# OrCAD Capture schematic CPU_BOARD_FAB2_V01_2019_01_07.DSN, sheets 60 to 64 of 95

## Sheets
60 045 DDR4 SODIMM CHA_1: size B
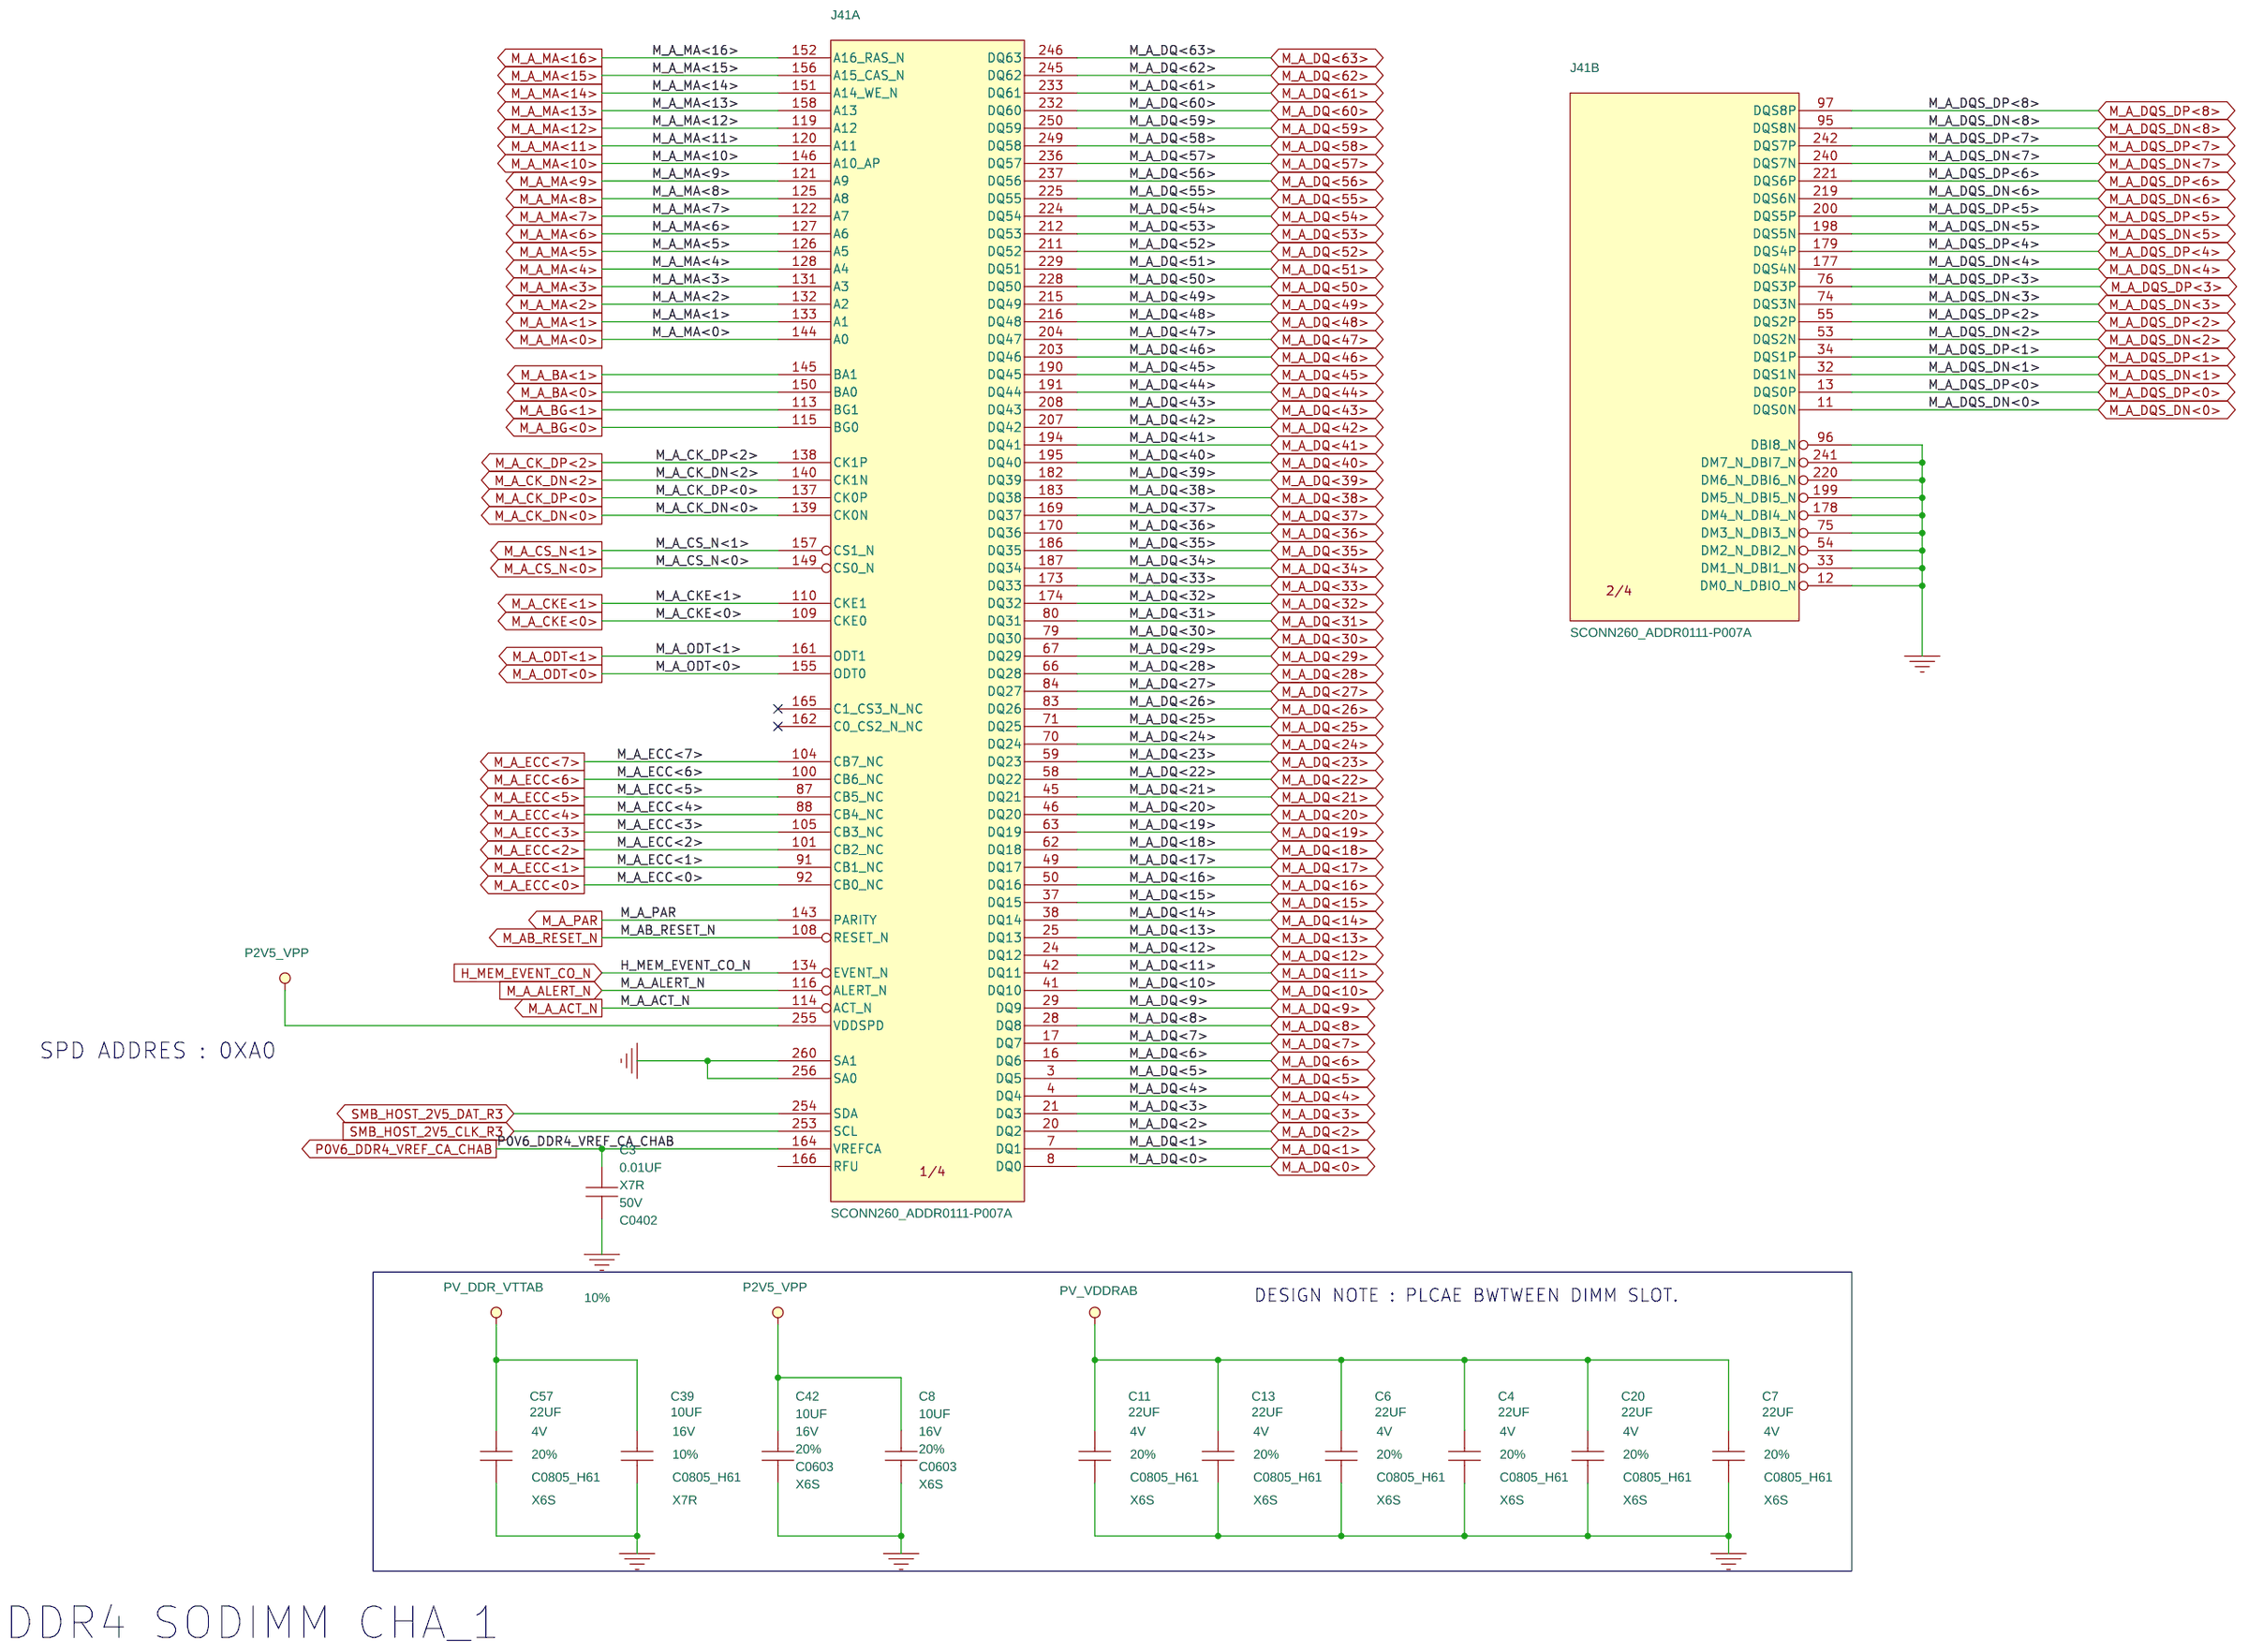
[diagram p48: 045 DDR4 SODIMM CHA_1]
61 047 DDR4 SODIMM CHB_1: size B
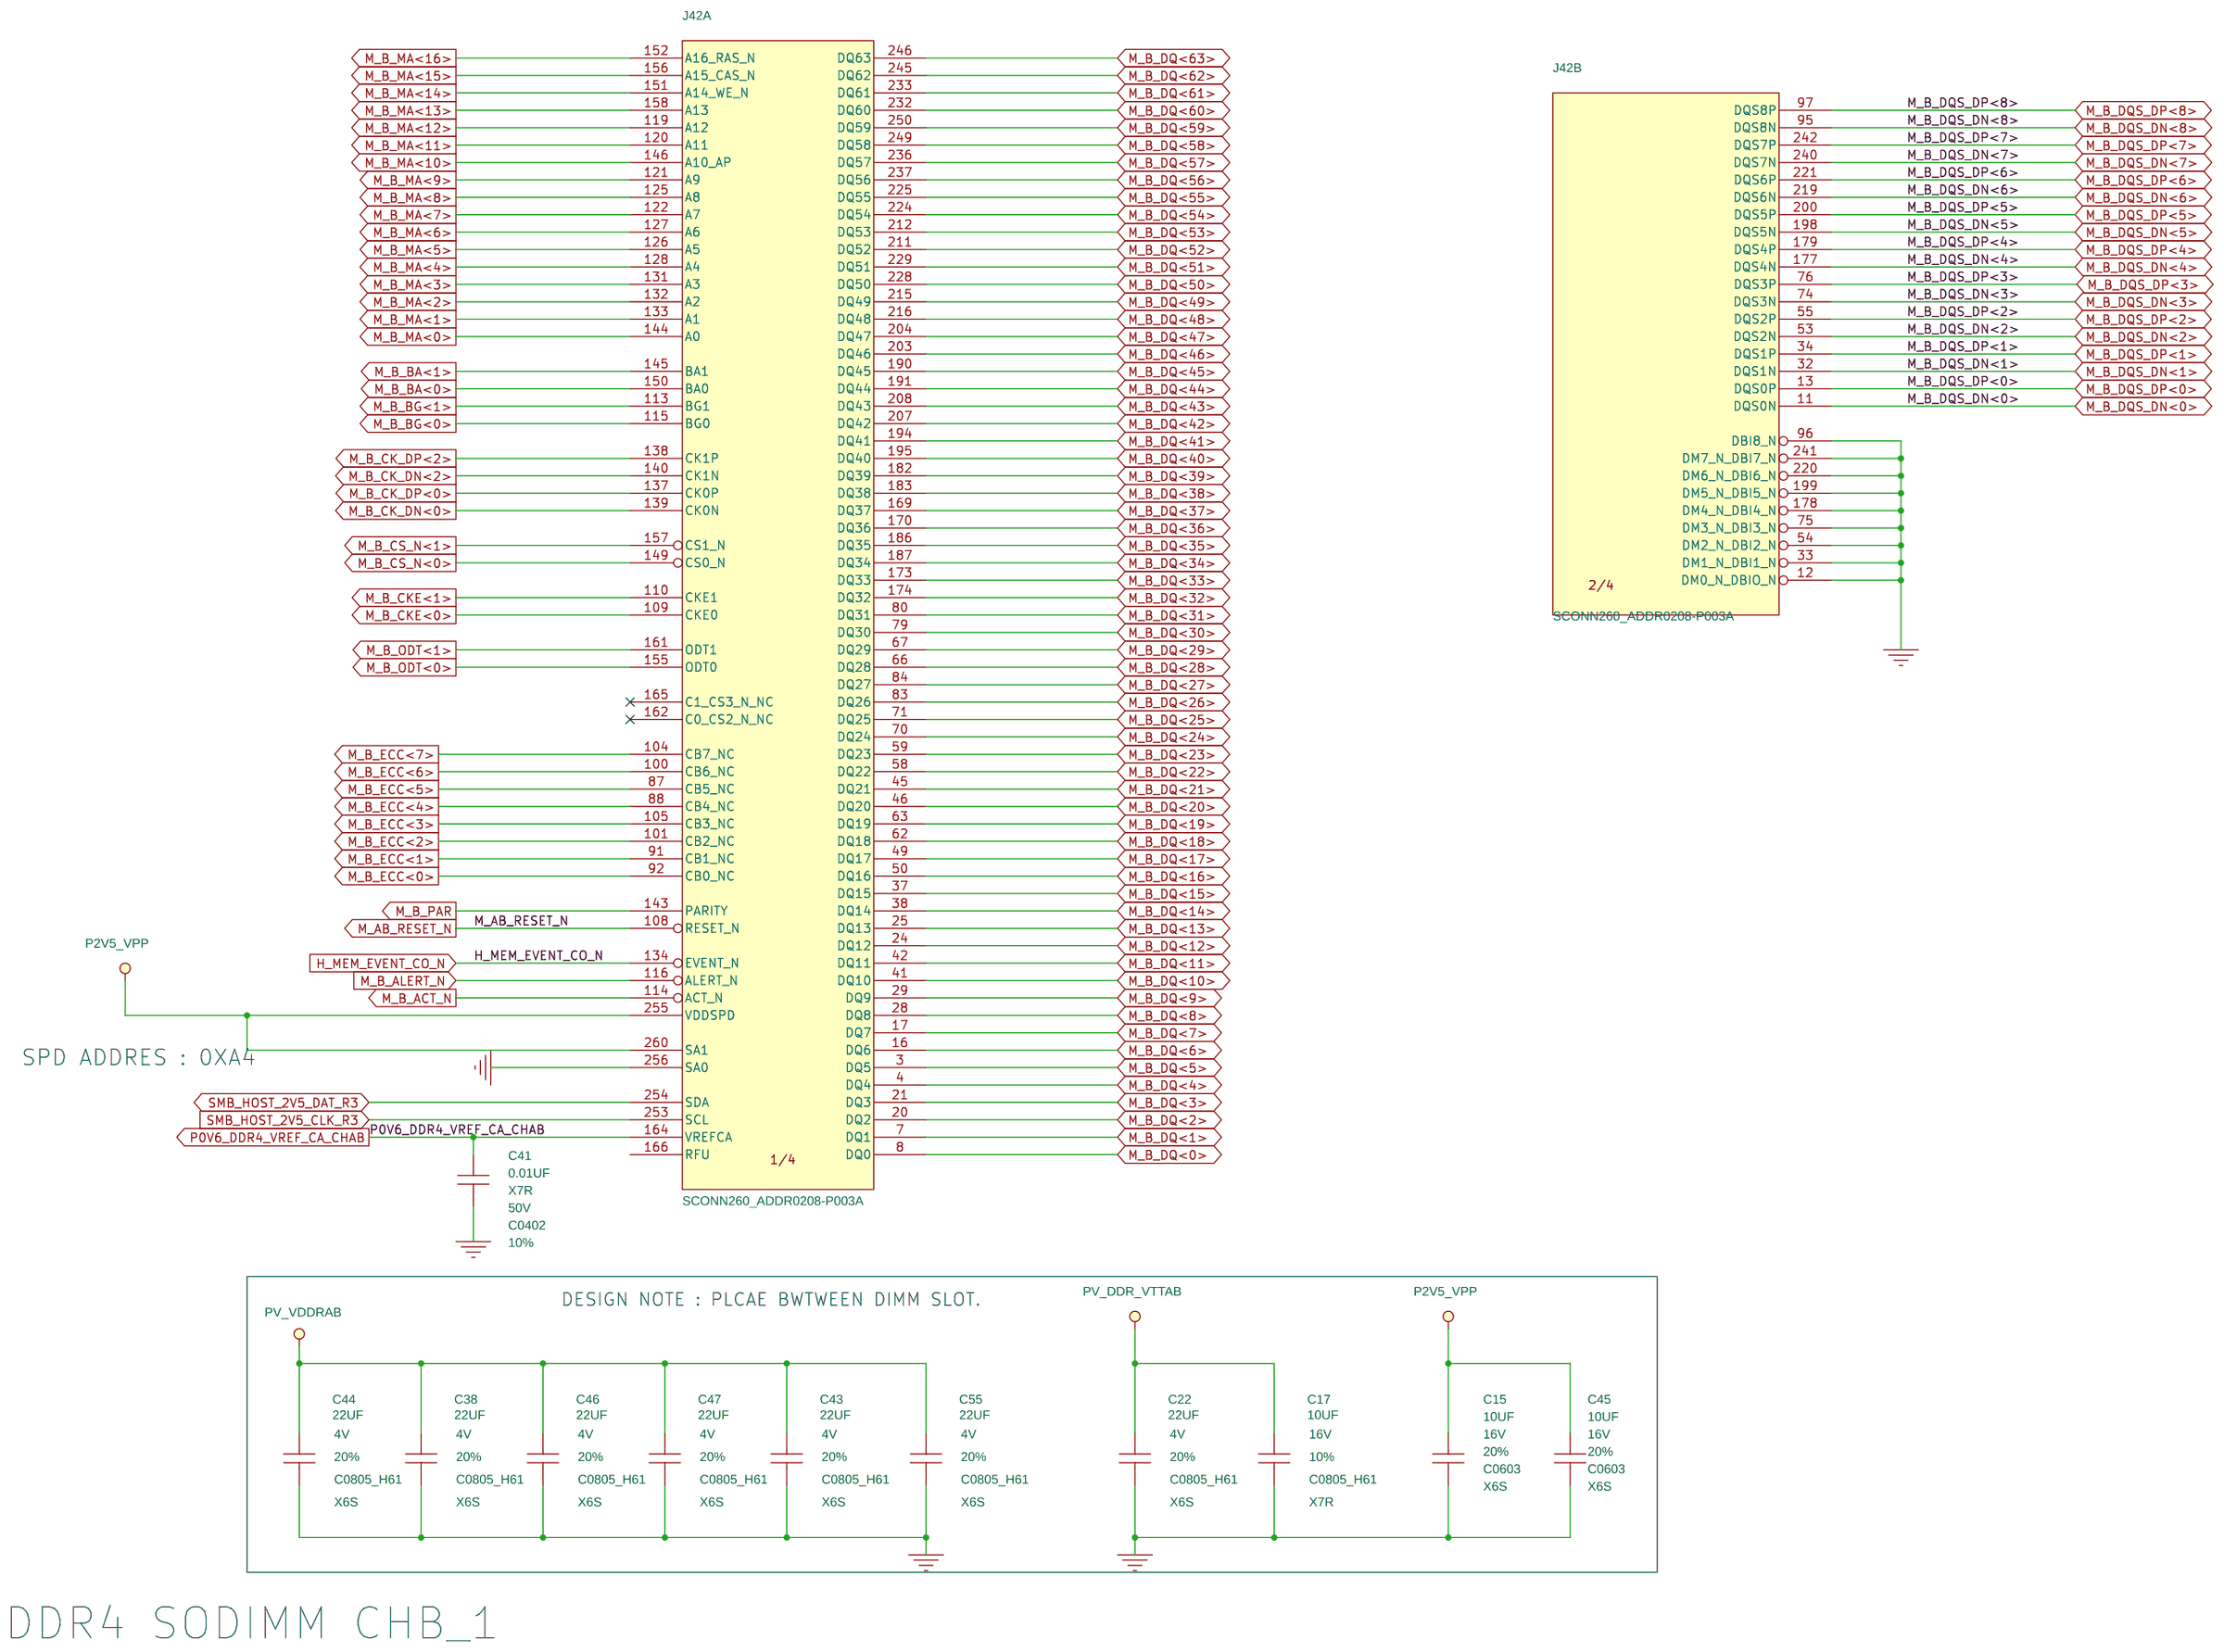
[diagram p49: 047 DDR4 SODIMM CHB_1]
62 049 TPM SLB9670: size B
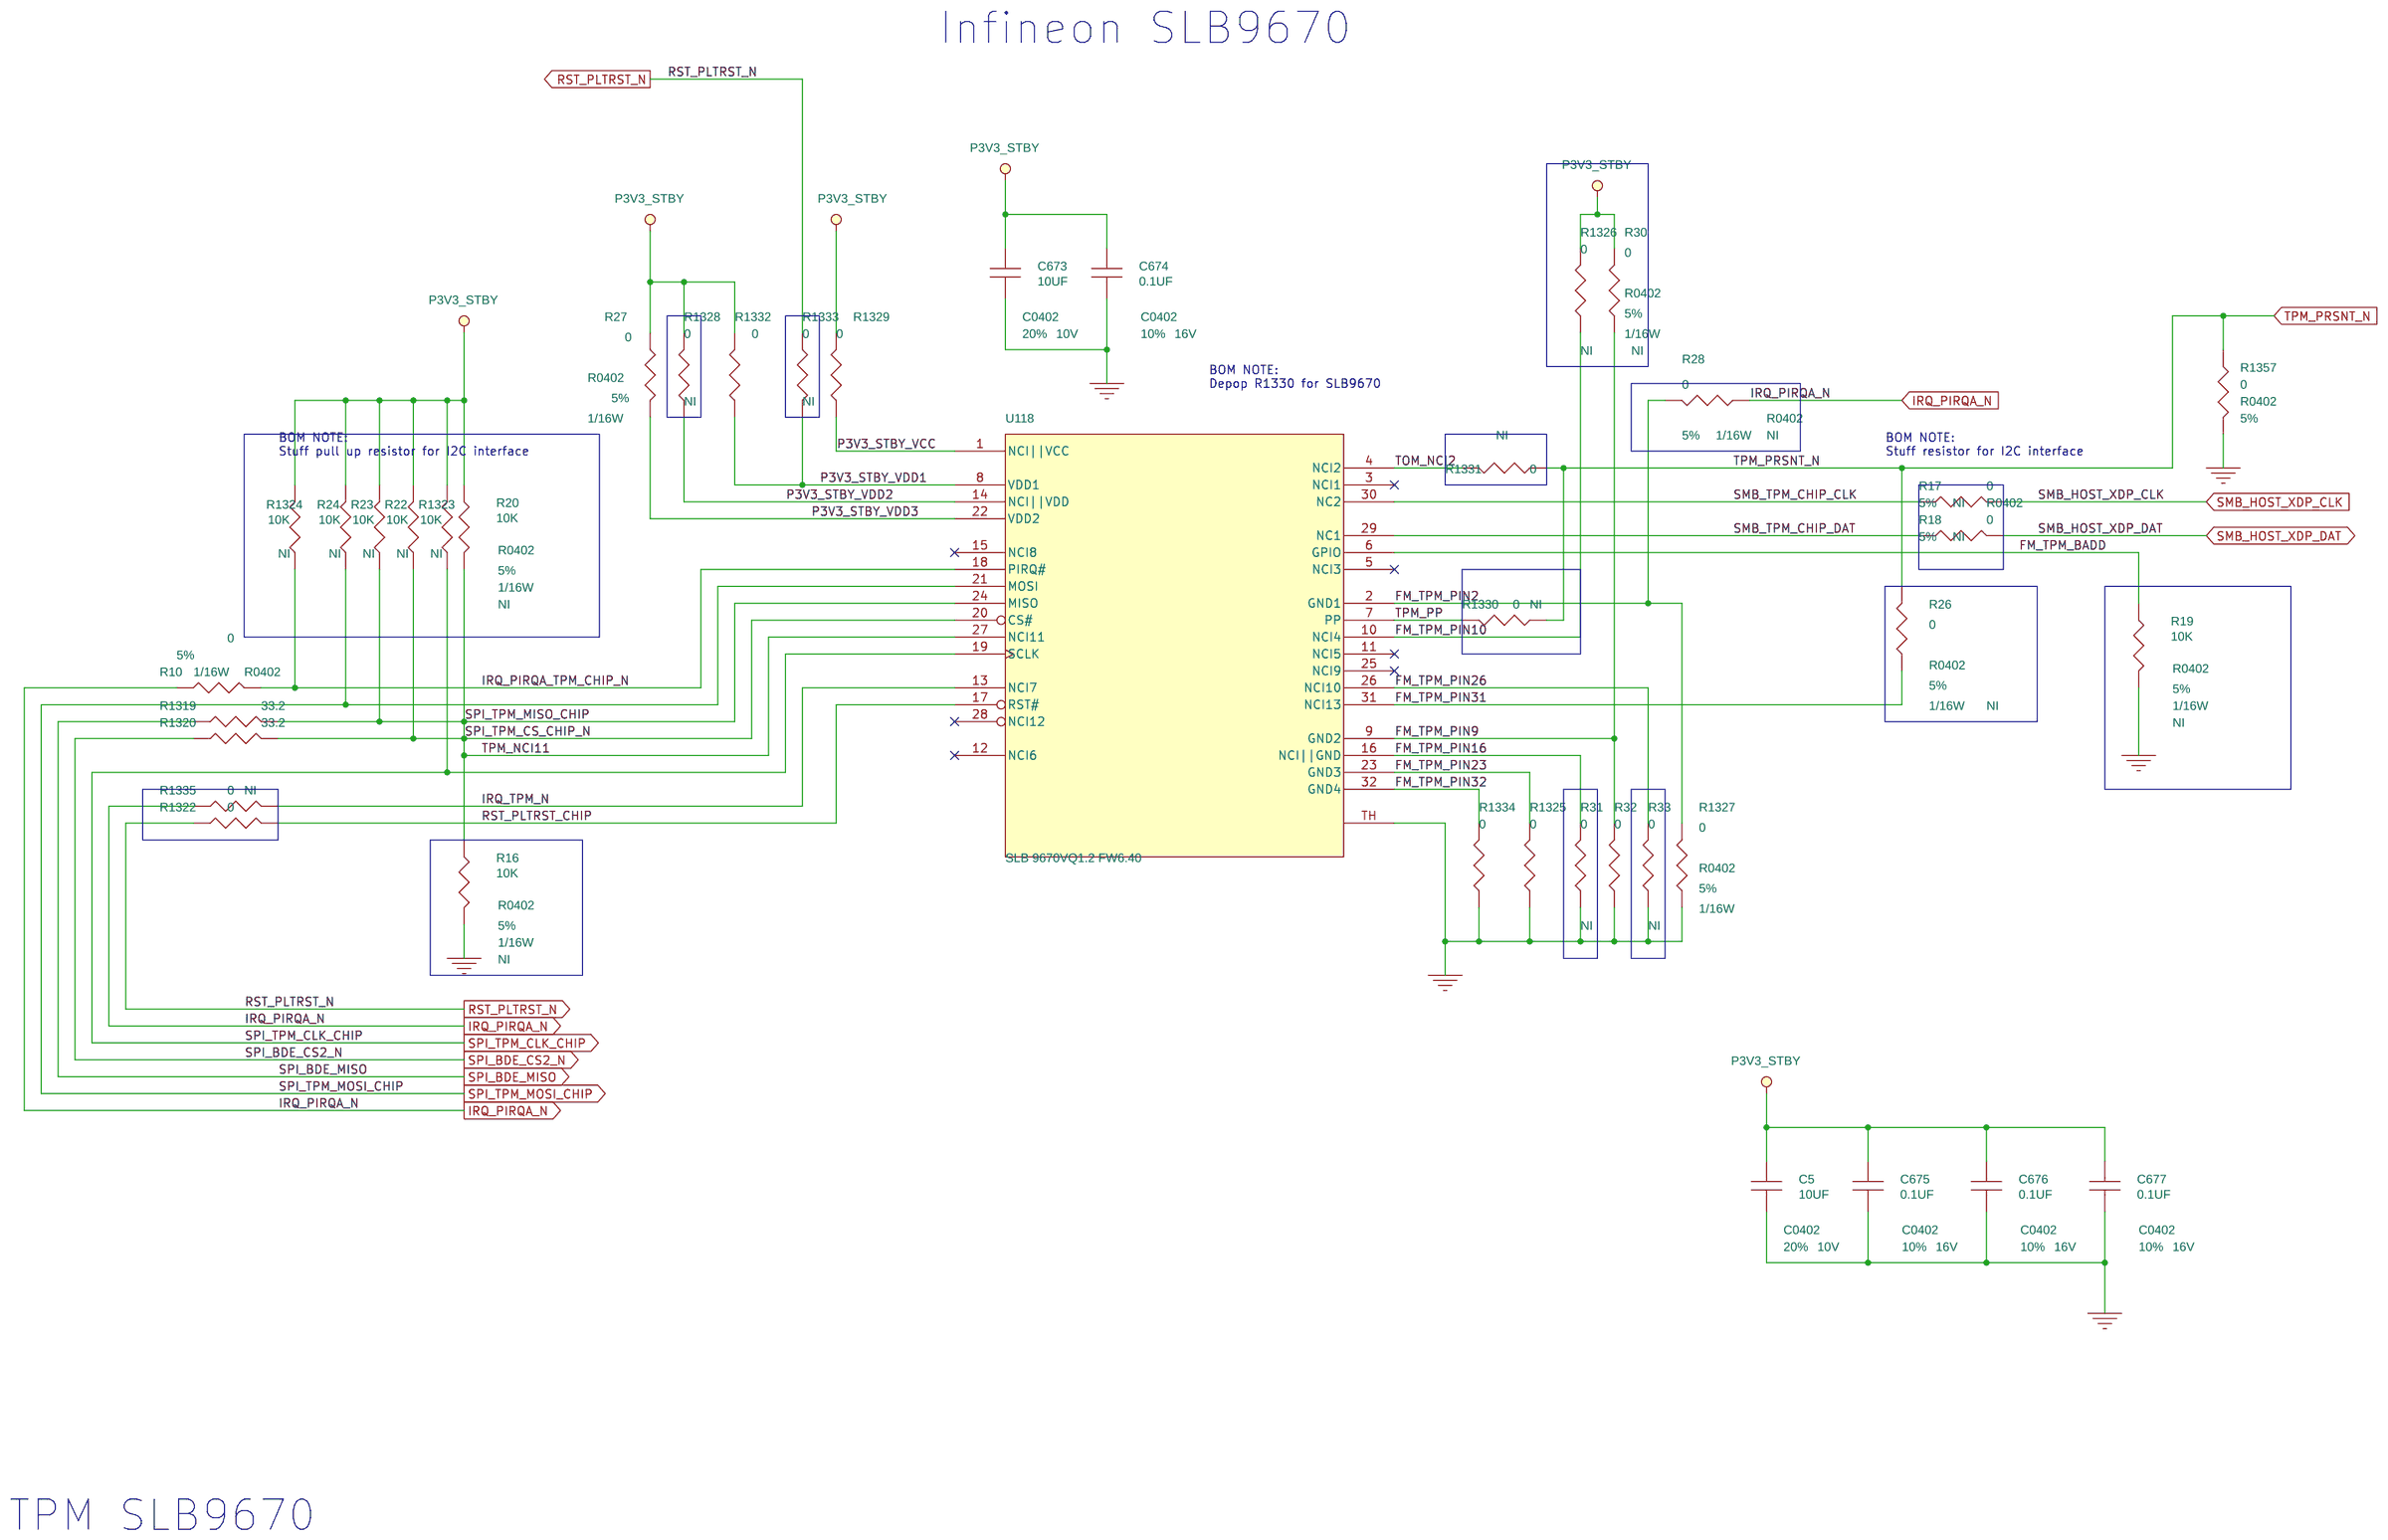
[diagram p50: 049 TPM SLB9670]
63 025 BDX-DE LPC,SPI,GPIO,INT_2: size B
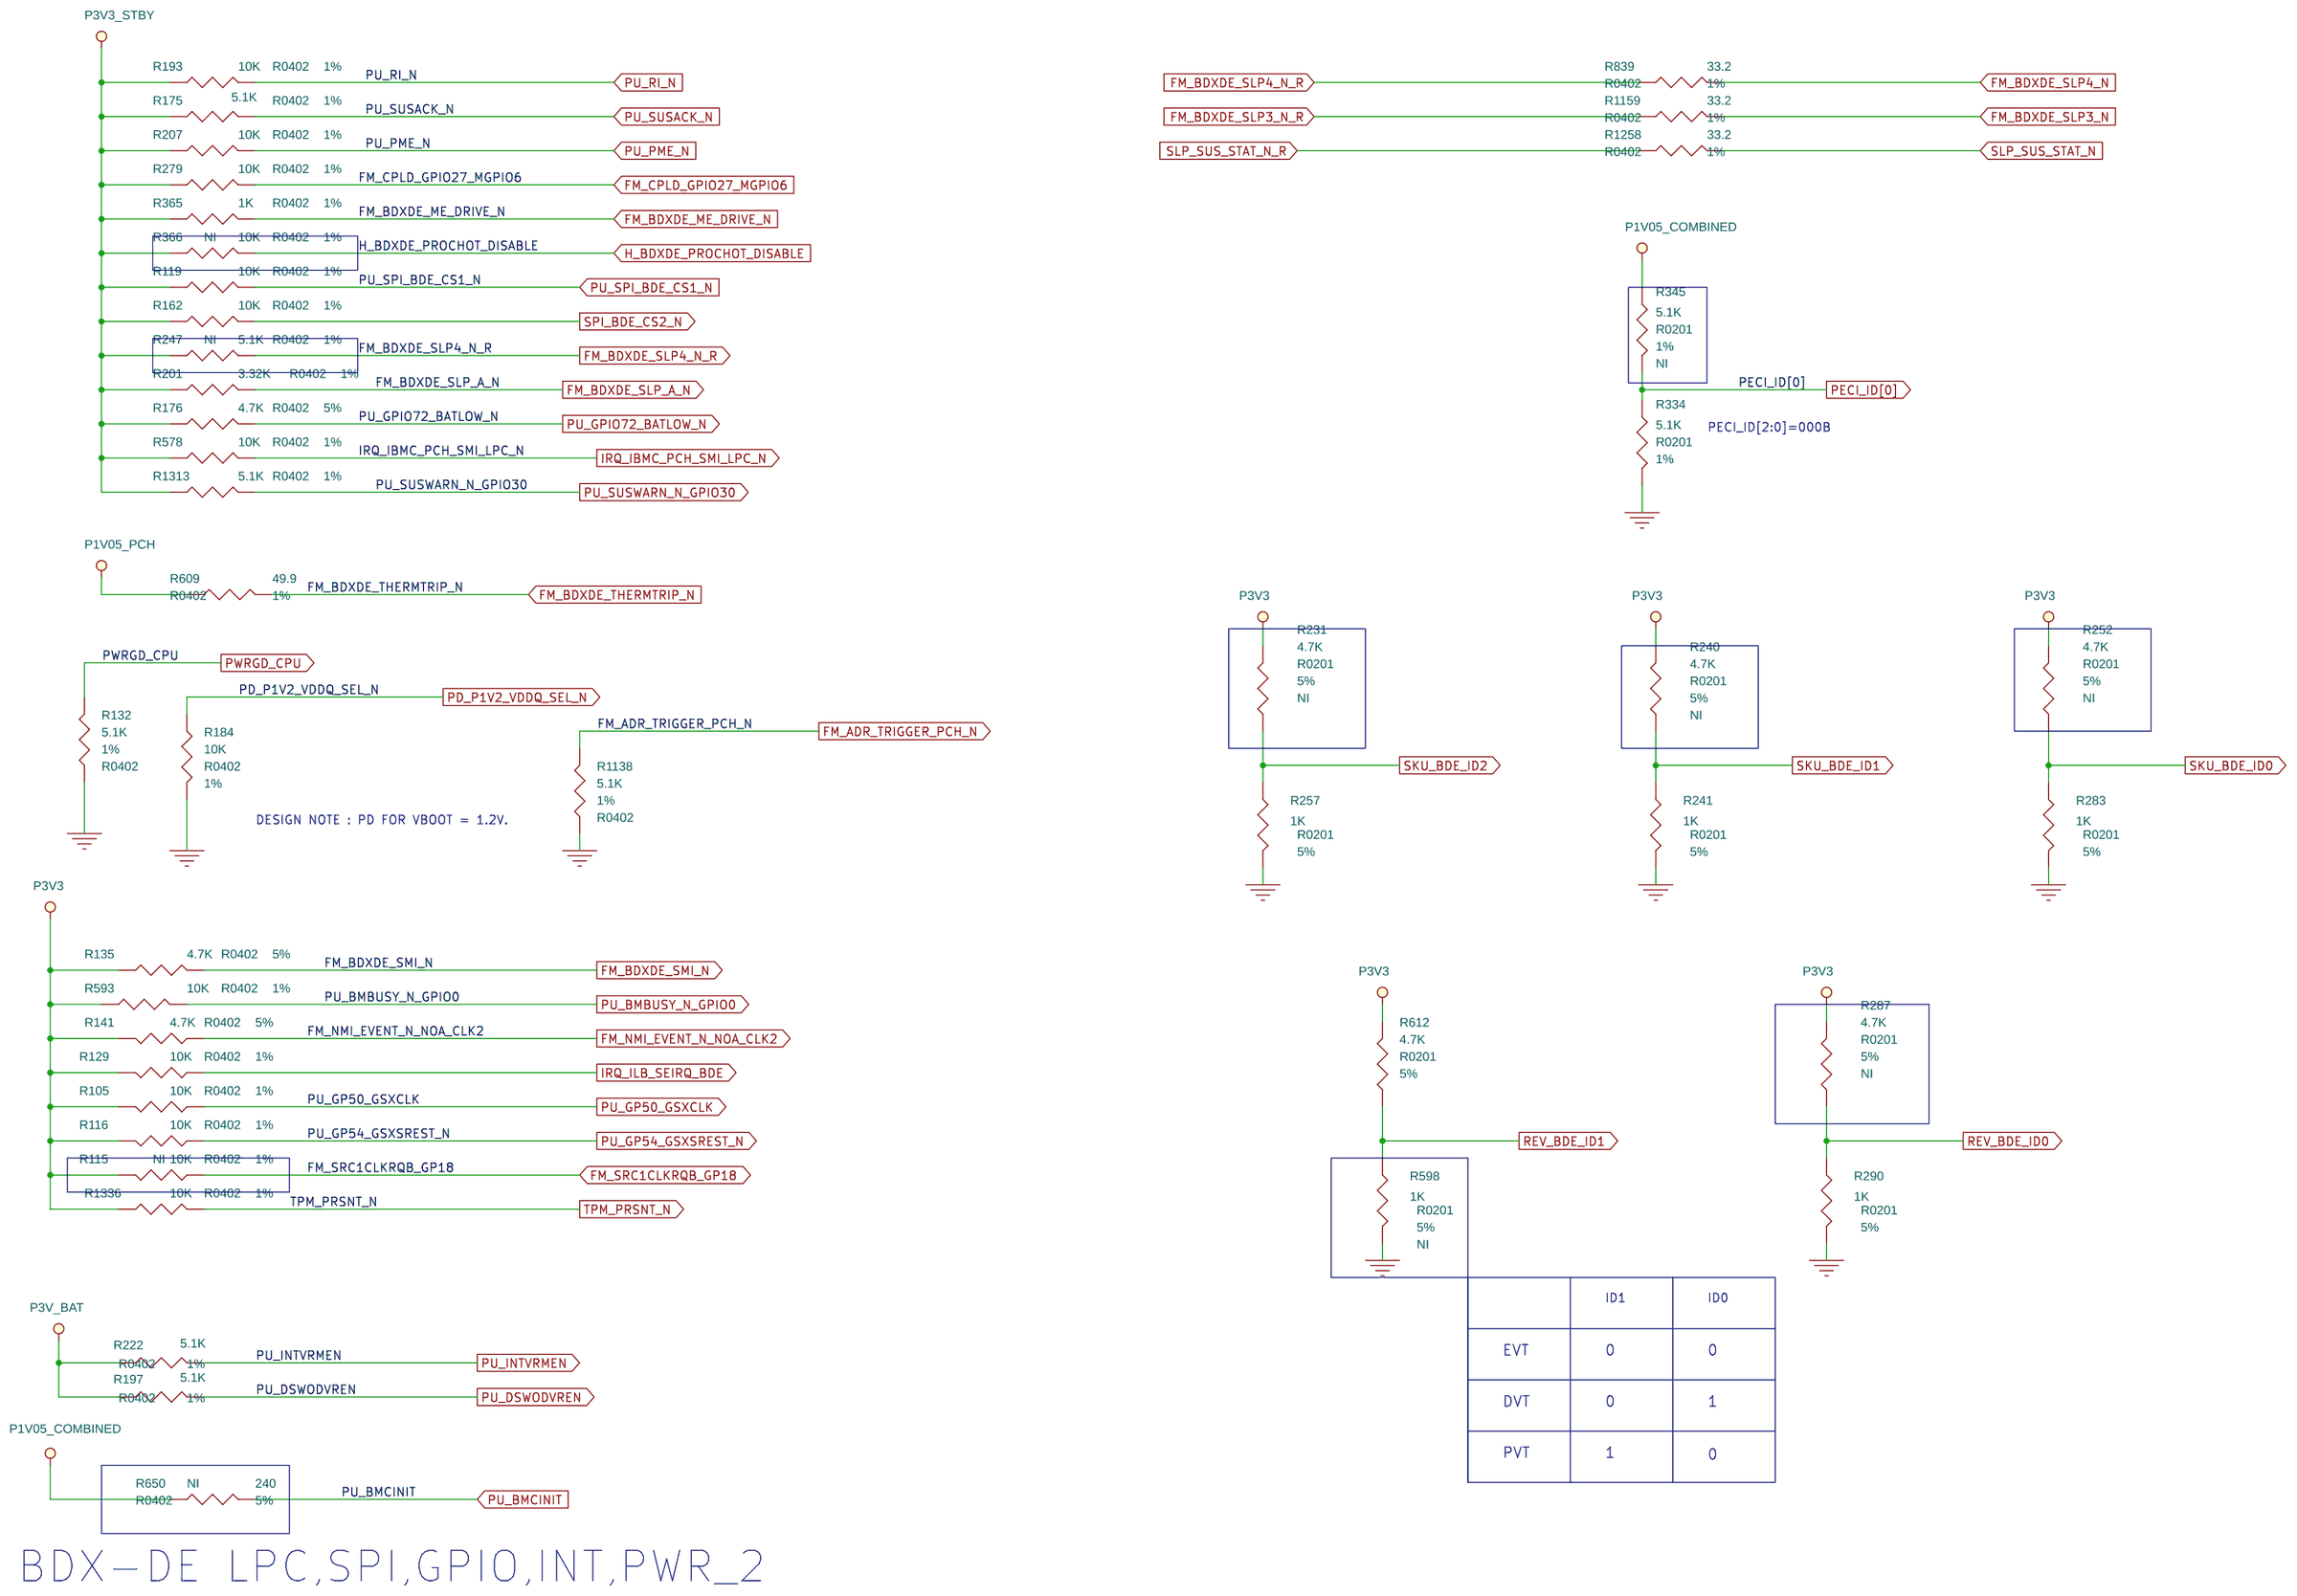
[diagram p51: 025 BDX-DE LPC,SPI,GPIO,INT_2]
64 051 CPLD_1: size B
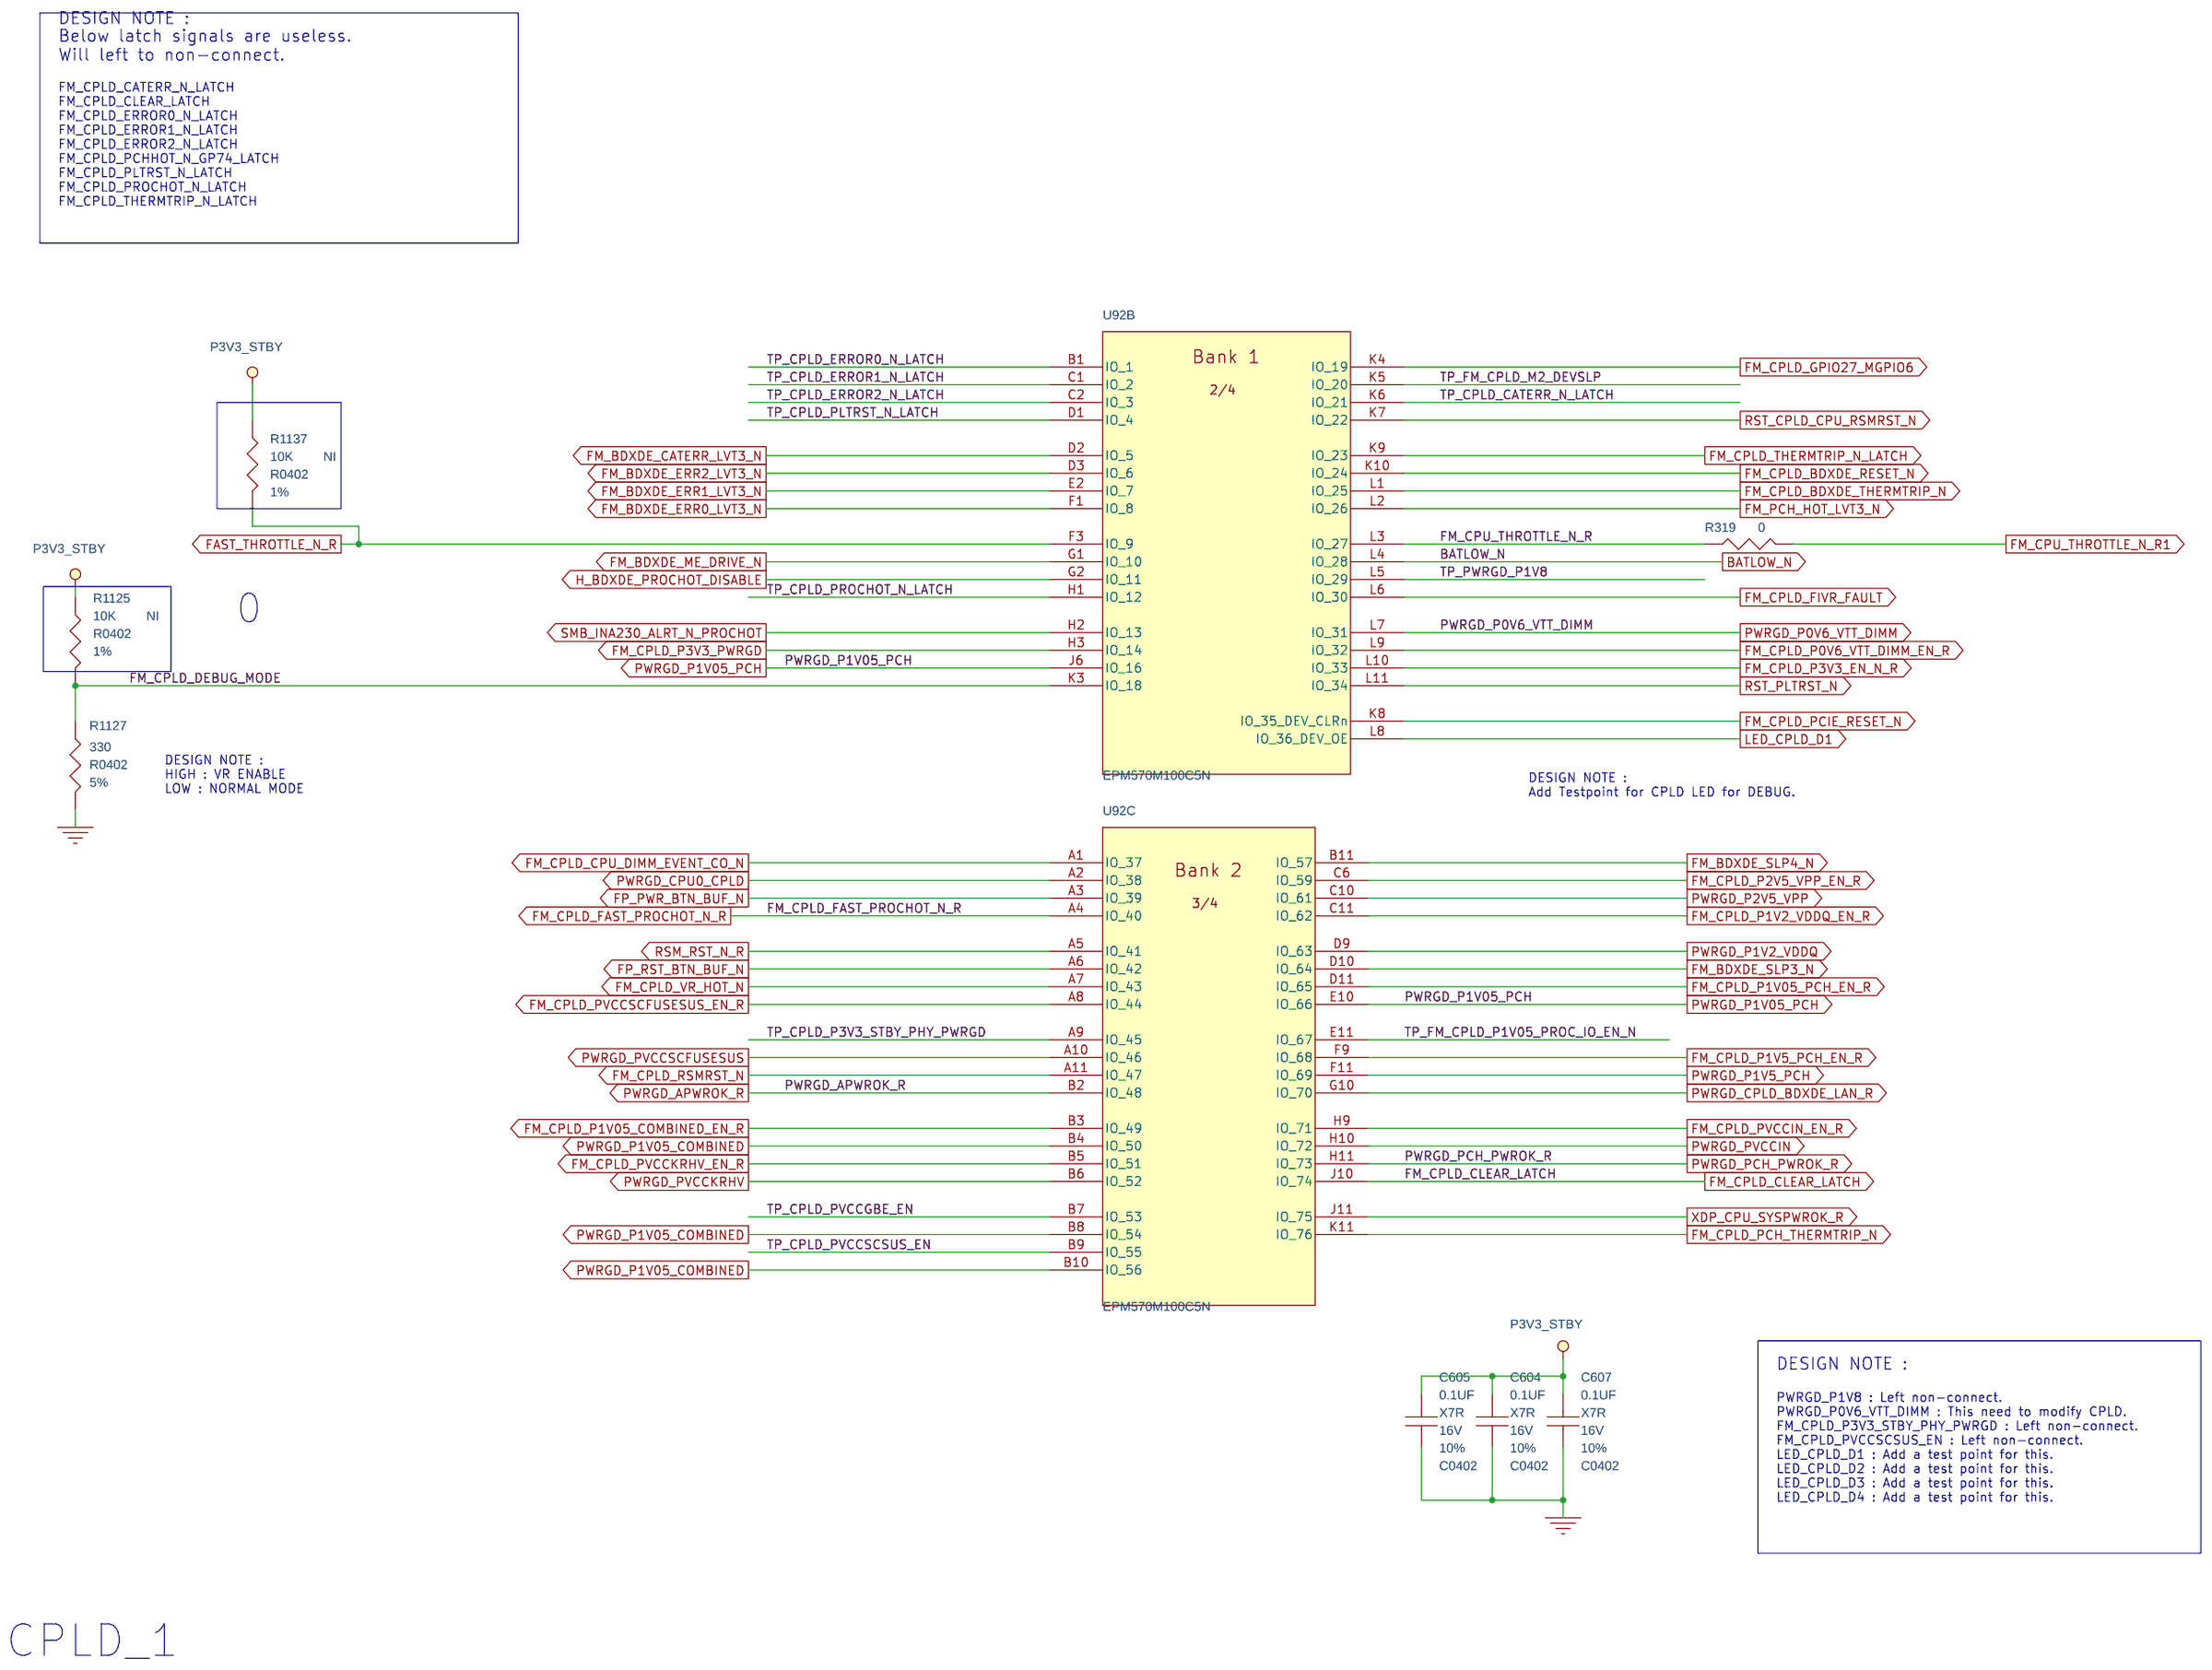
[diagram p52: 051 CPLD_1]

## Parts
sheet 025 BDX-DE LPC,SPI,GPIO,INT_2
R105  10K  [R0402]
R115  10K  [R0402]
R116  10K  [R0402]
R119  10K  [R0402]
R129  10K  [R0402]
R132  5.1K  [R0402]
R135  4.7K  [R0402]
R141  4.7K  [R0402]
R162  10K  [R0402]
R175  5.1K  [R0402]
R176  4.7K  [R0402]
R184  10K  [R0402]
R193  10K  [R0402]
R197  5.1K  [R0402]
R201  3.32K  [R0402]
R207  10K  [R0402]
R222  5.1K  [R0402]
R231  4.7K  [R0201]
R240  4.7K  [R0201]
R241  1K  [R0201]
R247  5.1K  [R0402]
R252  4.7K  [R0201]
R257  1K  [R0201]
R279  10K  [R0402]
R283  1K  [R0201]
R287  4.7K  [R0201]
R290  1K  [R0201]
R334  5.1K  [R0201]
R345  5.1K  [R0201]
R365  1K  [R0402]
R366  10K  [R0402]
R578  10K  [R0402]
R593  10K  [R0402]
R598  1K  [R0201]
R609  49.9  [R0402]
R612  4.7K  [R0201]
R650  240  [R0402]
R839  33.2  [R0402]
R1138  5.1K  [R0402]
R1159  33.2  [R0402]
R1258  33.2  [R0402]
R1313  5.1K  [R0402]
R1336  10K  [R0402]
sheet 045 DDR4 SODIMM CHA_1
C3  0.01UF  [C0402]
C4  22UF  [C0805_H61]
C6  22UF  [C0805_H61]
C7  22UF  [C0805_H61]
C8  10UF  [C0603]
C11  22UF  [C0805_H61]
C13  22UF  [C0805_H61]
C20  22UF  [C0805_H61]
C39  10UF  [C0805_H61]
C42  10UF  [C0603]
C57  22UF  [C0805_H61]
J41  SCONN260_ADDR0111-P007A  [SOCKET260S_RVSXH]  (sections A,B,C,D)
sheet 047 DDR4 SODIMM CHB_1
C15  10UF  [C0603]
C17  10UF  [C0805_H61]
C22  22UF  [C0805_H61]
C38  22UF  [C0805_H61]
C41  0.01UF  [C0402]
C43  22UF  [C0805_H61]
C44  22UF  [C0805_H61]
C45  10UF  [C0603]
C46  22UF  [C0805_H61]
C47  22UF  [C0805_H61]
C55  22UF  [C0805_H61]
J42  SCONN260_ADDR0208-P003A  [SOCKET260S_RVSXG]  (sections A,B,C,D)
sheet 049 TPM SLB9670
C5  10UF  [C0402]
C673  10UF  [C0402]
C674  0.1UF  [C0402]
C675  0.1UF  [C0402]
C676  0.1UF  [C0402]
C677  0.1UF  [C0402]
R10  0  [R0402]
R16  10K  [R0402]
R17  0  [R0402]
R18  0  [R0402]
R19  10K  [R0402]
R20  10K  [R0402]
R22  10K  [R0402]
R23  10K  [R0402]
R24  10K  [R0402]
R26  0  [R0402]
R27  0  [R0402]
R28  0  [R0402]
R30  0  [R0402]
R31  0  [R0402]
R32  0  [R0402]
R33  0  [R0402]
R1319  33.2  [R0402]
R1320  33.2  [R0402]
R1322  0  [R0402]
R1323  10K  [R0402]
R1324  10K  [R0402]
R1325  0  [R0402]
R1326  0  [R0402]
R1327  0  [R0402]
R1328  0  [R0402]
R1329  0  [R0402]
R1330  0  [R0402]
R1331  0  [R0402]
R1332  0  [R0402]
R1333  0  [R0402]
R1334  0  [R0402]
R1335  0  [R0402]
R1357  0  [R0402]
U118  SLB 9670VQ1.2 FW6.40  [VQFN32_TH_0-5_5X5]
sheet 051 CPLD_1
C604  0.1UF  [C0402]
C605  0.1UF  [C0402]
C607  0.1UF  [C0402]
R319  0  [R0402]
R1125  10K  [R0402]
R1127  330  [R0402]
R1137  10K  [R0402]
U92  EPM570M100C5N  [BGA100XD_SMDC9_SM9]  (sections A,B,C,D)

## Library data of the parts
R105 R116 R129 = R: RES CHIP 10K 1/16W +-1% (0402); CLASS: DISCRETE; CMPLS_LVL: EP; Data: WTC_LF_WR SERIES.pdf; From_pj: S82; Lifecycle: Comp-Approve; MATERIAL: CHIP; Manuf_PN: RR0510S-103-FN; Manuf_name: CYNTEC CO.. LTD.; Manufacturer: CYN; Manuftr: CYN; Part_Type: *LF_Resistor; Status: Preferred; TOLERANCE: 1%; WATTAGE: 1/16W; fp_ECN: 0402 SERIES_LL34.xls; top_bot: TOP
R115 = R: RES CHIP 10K 1/16W +-1% (0402); CLASS: DISCRETE; CMPLS_LVL: EP; Data: WTC_LF_WR SERIES.pdf; From_pj: S82; Lifecycle: Comp-Approve; MATERIAL: CHIP; Manuf_PN: RR0510S-103-FN; Manuf_name: CYNTEC CO.. LTD.; Manufacturer: CYN; Manuftr: CYN; Not_insert: NI; Part_Type: *LF_Resistor; Status: Preferred; TOLERANCE: 1%; WATTAGE: 1/16W; fp_ECN: 0402 SERIES_LL34.xls; top_bot: TOP
R119 R162 R184 R193 R207 R279 R578 R593 = R: RES CHIP 10K 1/16W +-1% (0402); CLASS: DISCRETE; CMPLS_LVL: EP; Data: WTC_LF_WR SERIES.pdf; From_pj: S82; Lifecycle: Comp-Approve; MATERIAL: CHIP; Manuf_PN: RR0510S-103-FN; Manuf_name: CYNTEC CO.. LTD.; Manuftr: CYN; Part_Type: *LF_Resistor; Status: Preferred; TOLERANCE: 1%; WATTAGE: 1/16W; fp_ECN: 0402 SERIES_LL34.xls
R132 R175 R197 R222 R1138 R1313 = R: RES CHIP 5.1K 1/16W +-1%(0402); CLASS: DISCRETE; CMPLS_LVL: EP; Data: MAT_LF_RES SERIES.pdf; From_pj: S10-ANTONY; Lifecycle: Comp-Approve; MATERIAL: CHIP; Manuf_PN: RR0510S-512-FN; Manuf_name: CYNTEC CO.. LTD.; Manuftr: CYN; Part_Type: *LF_Resistor; Status: Normal; TOLERANCE: 1%; WATTAGE: 1/16W; fp_ECN: 0402 SERIES_LL34.xls
R135 = R: RES CHIP 4.7K 1/16W +-5% (0402); CLASS: DISCRETE; CMPLS_LVL: EP; Data: WTC_LF_WR SERIES.pdf; Lifecycle: Comp-Approve; MATERIAL: CHIP; Manuf_PN: RR0510S-472-JN; Manuf_name: CYNTEC CO.. LTD.; Manuftr: CYN; Part_Type: *LF_Resistor; Status: Preferred; TOLERANCE: 5%; WATTAGE: 1/16W; fp_ECN: 0402 SERIES_LL34.xls
R141 = R: RES CHIP 4.7K 1/16W +-5% (0402); CLASS: DISCRETE; CMPLS_LVL: EP; Data: WTC_LF_WR SERIES.pdf; Lifecycle: Comp-Approve; MATERIAL: CHIP; Manuf_PN: RR0510S-472-JN; Manuf_name: CYNTEC CO.. LTD.; Manufacturer: CYN; Manuftr: CYN; Part_Type: *LF_Resistor; Status: Preferred; TOLERANCE: 5%; WATTAGE: 1/16W; fp_ECN: 0402 SERIES_LL34.xls; top_bot: TOP
R176 = R: RES CHIP 4.7K 1/16W +-5% (0402); CLASS: DISCRETE; CMPLS_LVL: EP; Data: WTC_LF_WR SERIES.pdf; Lifecycle: Comp-Approve; MATERIAL: CHIP; Manuf_PN: RR0510S-472-JN; Manuf_name: CYNTEC CO.. LTD.; Manufacturer: RLC; Manuftr: CYN; Part_Type: *LF_Resistor; Status: Preferred; TOLERANCE: 5%; WATTAGE: 1/16W; fp_ECN: 0402 SERIES_LL34.xls; top_bot: TOP
R201 = R: RES CHIP 3.32K 1/16W +-1% (0402); CLASS: DISCRETE; CMPLS_LVL: EP(V1); Data: WTC_WR04X4322FTL_REVL.pdf; From_pj: T2H-GAVEN; Lifecycle: Comp-Approve; MATERIAL: CHIP; Manuf_PN: WR04X3321FTL; Manuf_name: WALSIN TECHNOLOGY CORPORATION; Manufacturer: RLC; Manuftr: WTC; Part_Type: *LF_Resistor; RD_CMPLS_LVL: EP(V1); TOLERANCE: 1%; WATTAGE: 1/16W; fp_ECN: 0402 SERIES_LL34.xls; top_bot: TOP
R231 R240 R252 R287 = R: RES CHIP 4.7K(1/20W,+-5%,0201); CLASS: DISCRETE; CMPLS_LVL: EP(V1); Data: CYN_RL SERIES_revB0.pdf; From_pj: GD1-JACK; Lifecycle: Comp-Release Qty; MATERIAL: CHIP; Manuf_PN: RR0306S-472-JN; Manuf_name: CYNTEC CO., LTD.; Manufacturer: CYN; Manuftr: CYN; Not_insert: NI; Part_Type: *LF_Resistor; RD_CMPLS_LVL: EP(V1); TOLERANCE: 5%; WATTAGE: 1/20W; fp_ECN: DCN-all 0201 RCL part.doc; top_bot: BOT
R241 R257 R283 R290 = R: RES CHIP 1K 1/20W +-5%(0201)HF; CLASS: DISCRETE; CMPLS_LVL: EP(V1); Data: CYN_RL SERIES_revB0.pdf; From_pj: GD1-JACK; Lifecycle: Comp-Approve; MATERIAL: CHIP; Manuf_PN: RR0306S-102-JNH; Manuf_name: CYNTEC CO., LTD.; Manuftr: CYN; Part_Type: *LF_Resistor; RD_CMPLS_LVL: EP(V1); TOLERANCE: 5%; WATTAGE: 1/20W; fp_ECN: DCN-all 0201 RCL part.doc
R247 = R: RES CHIP 5.1K 1/16W +-1%(0402); CLASS: DISCRETE; CMPLS_LVL: EP; Data: MAT_LF_RES SERIES.pdf; From_pj: S10-ANTONY; Lifecycle: Comp-Approve; MATERIAL: CHIP; Manuf_PN: RR0510S-512-FN; Manuf_name: CYNTEC CO.. LTD.; Manuftr: CYN; Not_insert: NI; Part_Type: *LF_Resistor; Status: Normal; TOLERANCE: 1%; WATTAGE: 1/16W; fp_ECN: 0402 SERIES_LL34.xls
R334 = R: RES CHIP 5.1K 1/20W +-1%(0201); CLASS: DISCRETE; CMPLS_LVL: EP(V1); Data: YGO_LF_RES SERIES.pdf; From_pj: GD1-JACK; Lifecycle: Comp-Approve; MATERIAL: CHIP; Manuf_PN: RC0201FR-075K1L; Manuf_name: YAGEO CORPORATION; Manuftr: YGO; Part_Type: *LF_Resistor; RD_CMPLS_LVL: EP(V1); Standard: End of Design; TOLERANCE: 1%; WATTAGE: 1/20W; fp_ECN: DCN-all 0201 RCL part.doc
R345 = R: RES CHIP 5.1K 1/20W +-1%(0201); CLASS: DISCRETE; CMPLS_LVL: EP(V1); Data: YGO_LF_RES SERIES.pdf; From_pj: GD1-JACK; Lifecycle: Comp-Approve; MATERIAL: CHIP; Manuf_PN: RC0201FR-075K1L; Manuf_name: YAGEO CORPORATION; Manuftr: YGO; Not_insert: NI; Part_Type: *LF_Resistor; RD_CMPLS_LVL: EP(V1); Standard: End of Design; TOLERANCE: 1%; WATTAGE: 1/20W; fp_ECN: DCN-all 0201 RCL part.doc
R365 = R: RES CHIP 1K 1/16W +-1% (0402); CLASS: DISCRETE; CMPLS_LVL: EP; Data: WTC_LF_WR SERIES.pdf; Lifecycle: Comp-Approve; MATERIAL: CHIP; Manuf_PN: RR0510S-102-FN; Manuf_name: CYNTEC CO.. LTD.; Manuftr: CYN; Part_Type: *LF_Resistor; Status: Preferred; TOLERANCE: 1%; WATTAGE: 1/16W; fp_ECN: 0402 SERIES_LL34.xls
R366 R1125 R1137 = R: RES CHIP 10K 1/16W +-1% (0402); CLASS: DISCRETE; CMPLS_LVL: EP; Data: WTC_LF_WR SERIES.pdf; From_pj: S82; Lifecycle: Comp-Approve; MATERIAL: CHIP; Manuf_PN: RR0510S-103-FN; Manuf_name: CYNTEC CO.. LTD.; Manuftr: CYN; Not_insert: NI; Part_Type: *LF_Resistor; Status: Preferred; TOLERANCE: 1%; WATTAGE: 1/16W; fp_ECN: 0402 SERIES_LL34.xls
R598 = R: RES CHIP 1K 1/20W +-5%(0201)HF; CLASS: DISCRETE; CMPLS_LVL: EP(V1); Data: CYN_RL SERIES_revB0.pdf; From_pj: GD1-JACK; Lifecycle: Comp-Approve; MATERIAL: CHIP; Manuf_PN: RR0306S-102-JNH; Manuf_name: CYNTEC CO., LTD.; Manuftr: CYN; Not_insert: NI; Part_Type: *LF_Resistor; RD_CMPLS_LVL: EP(V1); TOLERANCE: 5%; WATTAGE: 1/20W; fp_ECN: DCN-all 0201 RCL part.doc
R609 = R: RES CHIP 49.9 1/16W +-1% (0402); CLASS: DISCRETE; CMPLS_LVL: EP; Data: WTC_LF_WR SERIES.pdf; Lifecycle: Comp-Approve; MATERIAL: CHIP; Manuf_PN: RR0510S-49R9-FN; Manuf_name: CYNTEC CO.. LTD.; Manuftr: CYN; Part_Type: *LF_Resistor; Status: Preferred; TOLERANCE: 1%; WATTAGE: 1/16W; fp_ECN: 0402 SERIES_LL34.xls
R612 = R: RES CHIP 4.7K(1/20W,+-5%,0201); CLASS: DISCRETE; CMPLS_LVL: EP(V1); Data: CYN_RL SERIES_revB0.pdf; From_pj: GD1-JACK; Lifecycle: Comp-Release Qty; MATERIAL: CHIP; Manuf_PN: RR0306S-472-JN; Manuf_name: CYNTEC CO., LTD.; Manufacturer: CYN; Manuftr: CYN; Part_Type: *LF_Resistor; RD_CMPLS_LVL: EP(V1); TOLERANCE: 5%; WATTAGE: 1/20W; fp_ECN: DCN-all 0201 RCL part.doc; top_bot: BOT
R650 = R: RES CHIP 240 1/16W +-5%(0402); CLASS: DISCRETE; CMPLS_LVL: EP; Data: YGO_RC0402 SERIES.pdf; From_pj: TU1B-MARTIN; Lifecycle: Comp-Approve; MATERIAL: CHIP; Manuf_PN: RC0402JR-07240RL; Manuf_name: YAGEO CORPORATION; Manuftr: YGO; Not_insert: NI; Part_Type: *LF_Resistor; RD_CMPLS_LVL: EP; TOLERANCE: 5%; WATTAGE: 1/16W; fp_ECN: 0402 SERIES_LL34.xls
R839 R1159 R1258 = R: RES CHIP 33.2 1/16W +-1%(0402); CLASS: DISCRETE; CMPLS_LVL: EP; Data: CYN_LF_RL SERIES.pdf; From_pj: A06-EDISON; Lifecycle: Comp-Approve; MATERIAL: CHIP; Manuf_PN: RR0510S-33R2-FN; Manuf_name: CYNTEC CO.. LTD.; Manuftr: CYN; Part_Type: *LF_Resistor; TOLERANCE: 1%; WATTAGE: 1/16W; fp_ECN: 0402 SERIES_LL34.xls
R1336 = R: RES CHIP 10K 1/16W +-1% (0402); CLASS: DISCRETE; CMPLS_LVL: EP; Data: WTC_LF_WR SERIES.pdf; From_pj: S82; Lifecycle: Comp-Approve; MATERIAL: CHIP; Manuf_PN: RR0510S-103-FN; Manuf_name: CYNTEC CO.. LTD.; Manufacturer: CYN; Manuftr: CYN; Part_Type: *LF_Resistor; SIDE: BOT; Status: Preferred; TOLERANCE: 1%; WATTAGE: 1/16W; fp_ECN: 0402 SERIES_LL34.xls
C3 C41 = CAP_NP: CAP CHIP 0.01U 50V(+-10%,X7R,0402); CLASS: DISCRETE; CMPLS_LVL: EP(V1); Data: MUR_MLCC_20110826.pdf; From_pj: T2B-CHEESE; Lifecycle: Comp-Approve; MATERIAL: X7R; Manuf_PN: WBM155R71H103K; Manuf_name: MURATA ERIE N.A. INC TAIWAN BRANCH Okayama Murata Mfg.Co.,Ltd.; Manufacturer: MUR; Manuftr: MUR; Part_Type: *LF_C0402; RD_CMPLS_LVL: EP(V1); ROOM: VR_P1V05_PCH; TOLERANCE: 10%; Top_bot: TOP; VOLTAGE: 50V; fp_ECN: 0402 SERIES_LL34.xls
C4 C6 C7 C11 C13 C20 C22 C38 C43 C44 C46 C47 C55 C57 = CAP_NP: CAP CHIP 22U 4V(+-20%.X6S.0805); CLASS: DISCRETE; CMPLS_LVL: EP; Data: MUR_LF_CAP SERIES_2.pdf; From_pj: S50-STEVE; Lifecycle: Comp-Approve; MATERIAL: X6S; Manuf_PN: GRM21BC80G226M; Manuf_name: MURATA ERIE N.A. INC TAIWAN BRANCH Okayama Murata Mfg.Co..Ltd.Wakura Murata Mfg.; Manuftr: MUR; Part_Type: *LF_C0805; Standard: End of Design; TOLERANCE: 20%; VOLTAGE: 4V
C8 C15 C42 C45 = CAP_NP: CAP CHIP 10U 16V(+-20%,X6S,0603); CLASS: DISCRETE; CMPLS_LVL: EP(V1); Data: MUR_GRM188C81C106M.pdf; From_pj: JB9T-YUI-LIN; Lifecycle: Comp-Approve; MATERIAL: X6S; Manuf_PN: GRM188C81C106M; Manuf_name: MURATA ERIE N.A. INC TAIWAN BRANCH Okayama Murata Mfg.Co..Ltd. Wakura Murata Mfg; Manuftr: MUR; Part_Type: *LF_C0603; RD_CMPLS_LVL: EP(V1); TOLERANCE: 20%; VOLTAGE: 16V
C17 C39 = CAP_NP: CAP CHIP 10UF 16V(+-10%,X7R,0805); CLASS: DISCRETE; CMPLS_LVL: EP(V1); Data: SAM_MLCC SERIES_20130308.pdf; From_pj: T2H-CHEESE; Lifecycle: Comp-Approve; MATERIAL: X7R; Manuf_PN: CL21B106KOQNNNE; Manuf_name: SAMSUNG ELECTRONICS CO.,LTD; Manuftr: SAM; Part_Type: *LF_C0805; RD_CMPLS_LVL: EP(V1); TOLERANCE: 10%; VOLTAGE: 16V
J41 = SCONN260_ADDR0106P003A: CONN SMD HS DDR4 260P 2R FR(P0.5,H9.2); CLASS: IO; Data: LTS_ADDR0111-P007A.pdf; From_pj: T6A-TONY; Lifecycle: Comp-Release Qty; MATERIAL: IO; Manuf_PN: ADDR0111-P007A; Manuf_name: LOTES(CHIA TSE TERMINAL INDUSTRYLOTES SUZHOU CO.,; Manuftr: LTS; Part_Type: *LF_Connector; RD_CMPLS_LVL: EP(V1)
J42 = SCONN260_ADDR0106P003A: CONN SMD HS DDR4 260P 2R FR(P0.5,H5.2); CLASS: IO; Data: LTS_ADDR0208-P003A.pdf; From_pj: T6A-TONY; Lifecycle: Comp-Release Qty; MATERIAL: IO; Manuf_PN: ADDR0208-P003A; Manuf_name: LOTES(CHIA TSE TERMINAL INDUSTRYLOTES SUZHOU CO.,; Manuftr: LTS; Part_Type: *LF_Connector; RD_CMPLS_LVL: EP(V1)
C5 C673 = CAP_NP: CAP CHIP 10U 10V (+-20%, X5R, 0402); CLASS: DISCRETE; Data: CL05A106MP5NUNC.pdf; From_pj: T6VA-RAYMOND; Lifecycle: Comp-Approve; MATERIAL: X5R; Manuf_PN: CL05A106MP5NUNC; Manuf_name: SAMSUNG ELECTRONICS CO.,LTD (Samsung Mobile Display) / SAMSUNG SDI CO.,LTD; Manuftr: SAM; Part_Type: *LF_C0402; RD_CMPLS_LVL: EP(V1); TOLERANCE: 20%; TOP_BOT: BOT; VOLTAGE: 10V; fp_ECN: 0402 SERIES_LL34.xls
C674-C677 = CAP_NP: CAP CHIP 0.1U 16V(10%.X7R.0402); CLASS: DISCRETE; CMPLS_LVL: EP(V1); Data: MUR_LF_CAP SERIES_1.pdf; FPLIST: C0402,C0402_OCTAGONXA; From_pj: S5A-TRAVIS; Lifecycle: Comp-Approve; MATERIAL: X7R; Manuf_PN: WBM155R71C104K; Manuf_name: MURATA ERIE N.A. INC TAIWAN BRANCH Okayama Murata Mfg.Co..Ltd. Wakura Murata Mfg; Manuftr: MUR; Part_Type: *LF_C0402; RD_CMPLS_LVL: EP(V1); TOLERANCE: 10%; TOP_BOT: BOT; VOLTAGE: 16V; fp_ECN: 0402 SERIES_LL34.xls
R10 R32 R1325 R1334 = R: RESISTOR CHIP 0 1/16W +-5%(0402); CLASS: DISCRETE; CMPLS_LVL: EP; Data: WTC_LF_WR SERIES.pdf; Lifecycle: Comp-Approve; MATERIAL: CHIP; Manuf_PN: RR0510X-000-XN; Manuf_name: CYNTEC CO.. LTD.; Manuftr: CYN; Part_Type: *LF_Resistor; Status: Preferred; TOLERANCE: 5%; TOP_BOT: TOP; WATTAGE: 1/16W; fp_ECN: 0402 SERIES_LL34.xls
R16 R20 R22-R24 R1323 = R: RES CHIP 10K 1/16W 5%(0402); CLASS: DISCRETE; CMPLS_LVL: EP; Data: WTC_LF_WR SERIES.pdf; Lifecycle: Comp-Approve; MATERIAL: CHIP; Manuf_PN: RR0510S-103-JN; Manuf_name: CYNTEC CO.. LTD.; Manuftr: CYN; Not_insert: NI; Part_Type: *LF_Resistor; Status: Preferred; TOLERANCE: 5%; TOP_BOT: BOT; WATTAGE: 1/16W; fp_ECN: 0402 SERIES_LL34.xls
R17 R18 R26 R31 R33 R1335 = R: RESISTOR CHIP 0 1/16W +-5%(0402); CLASS: DISCRETE; CMPLS_LVL: EP; Data: WTC_LF_WR SERIES.pdf; Lifecycle: Comp-Approve; MATERIAL: CHIP; Manuf_PN: RR0510X-000-XN; Manuf_name: CYNTEC CO.. LTD.; Manuftr: CYN; Not_insert: NI; Part_Type: *LF_Resistor; Status: Preferred; TOLERANCE: 5%; TOP_BOT: TOP; WATTAGE: 1/16W; fp_ECN: 0402 SERIES_LL34.xls
R19 R1324 = R: RES CHIP 10K 1/16W 5%(0402); CLASS: DISCRETE; CMPLS_LVL: EP; Data: WTC_LF_WR SERIES.pdf; Lifecycle: Comp-Approve; MATERIAL: CHIP; Manuf_PN: RR0510S-103-JN; Manuf_name: CYNTEC CO.. LTD.; Manuftr: CYN; Not_insert: NI; Part_Type: *LF_Resistor; Status: Preferred; TOLERANCE: 5%; TOP_BOT: TOP; WATTAGE: 1/16W; fp_ECN: 0402 SERIES_LL34.xls
R27 R1322 R1327 R1329 R1332 = R: RESISTOR CHIP 0 1/16W +-5%(0402); CLASS: DISCRETE; CMPLS_LVL: EP; Data: WTC_LF_WR SERIES.pdf; Lifecycle: Comp-Approve; MATERIAL: CHIP; Manuf_PN: RR0510X-000-XN; Manuf_name: CYNTEC CO.. LTD.; Manuftr: CYN; Part_Type: *LF_Resistor; Status: Preferred; TOLERANCE: 5%; TOP_BOT: BOT; WATTAGE: 1/16W; fp_ECN: 0402 SERIES_LL34.xls
R28 R30 R1326 R1328 R1330 R1331 R1333 = R: RESISTOR CHIP 0 1/16W +-5%(0402); CLASS: DISCRETE; CMPLS_LVL: EP; Data: WTC_LF_WR SERIES.pdf; Lifecycle: Comp-Approve; MATERIAL: CHIP; Manuf_PN: RR0510X-000-XN; Manuf_name: CYNTEC CO.. LTD.; Manuftr: CYN; Not_insert: NI; Part_Type: *LF_Resistor; Status: Preferred; TOLERANCE: 5%; TOP_BOT: BOT; WATTAGE: 1/16W; fp_ECN: 0402 SERIES_LL34.xls
R1319 R1320 = R: RES CHIP 33.2 1/16W +-1%(0402); CLASS: DISCRETE; CMPLS_LVL: EP; Data: CYN_LF_RL SERIES.pdf; From_pj: A06-EDISON; Lifecycle: Comp-Approve; MATERIAL: CHIP; Manuf_PN: RR0510S-33R2-FN; Manuf_name: CYNTEC CO.. LTD.; Manuftr: CYN; Part_Type: *LF_Resistor; TOLERANCE: 1%; TOP_BOT: TOP; WATTAGE: 1/16W; fp_ECN: 0402 SERIES_LL34.xls
R319 R1357 = R: RESISTOR CHIP 0 1/16W +-5%(0402); CLASS: DISCRETE; CMPLS_LVL: EP; Data: WTC_LF_WR SERIES.pdf; Lifecycle: Comp-Approve; MATERIAL: CHIP; Manuf_PN: RR0510X-000-XN; Manuf_name: CYNTEC CO.. LTD.; Manuftr: CYN; Part_Type: *LF_Resistor; Status: Preferred; TOLERANCE: 5%; WATTAGE: 1/16W; fp_ECN: 0402 SERIES_LL34.xls
U118 = SLB9670VQ12FW640: IC OTHER(32P)SLB9670VQ1.2 FW 06.40(VQFN); CLASS: IC; CMPLS_LVL: EP(V1); Data: SNI_SLB9670VQ1.2FW6.40.pdf; From_pj: F08-SHERRY; Lifecycle: Comp-Approve; MATERIAL: IC; Manuf_name: INFINEON TECHNOLOGIES ASIA PACIFIC; Manuftr: SNI; Part_Type: *LF_Chipset; RD_CMPLS_LVL: EP(V1); Standard: Non-Preferred; TOP_BOT: BOT
C604 C605 C607 = CAP_NP: CAP CHIP 0.1U 16V(10%.X7R.0402); CLASS: DISCRETE; CMPLS_LVL: EP(V1); Data: MUR_LF_CAP SERIES_1.pdf; From_pj: S5A-TRAVIS; Lifecycle: Comp-Approve; MATERIAL: X7R; Manuf_PN: WBM155R71C104K; Manuf_name: MURATA ERIE N.A. INC TAIWAN BRANCH Okayama Murata Mfg.Co..Ltd. Wakura Murata Mfg; Manufacturer: MUR; Manuftr: MUR; Part_Type: *LF_C0402; RD_CMPLS_LVL: EP(V1); TOLERANCE: 10%; VOLTAGE: 16V; fp_ECN: 0402 SERIES_LL34.xls
R1127 = R: RES CHIP 330(1/16W +-5% 0402); CLASS: DISCRETE; CMPLS_LVL: EP; Data: WTC_LF_WR SERIES.pdf; Lifecycle: Comp-Approve; MATERIAL: CHIP; Manuf_PN: RR0510S-331-JN; Manuf_name: CYNTEC CO.. LTD.; Manuftr: CYN; Part_Type: *LF_Resistor; Status: Preferred; TOLERANCE: 5%; WATTAGE: 1/16W; fp_ECN: 0402 SERIES_LL34.xls
U92 = EPM570M100C5N: PROG IC (100P) EPM240M100C5N (MBGA); CLASS: IC; Data: ATA_EPM570M100C5N.pdf; From_pj: S2B-HANK; Lifecycle: Comp-Approve; MATERIAL: IC; Manuf_name: ALTERA; Manuftr: ATA; Part_Type: *LF_Chipset; RD_CMPLS_LVL: EU(V1); Standard: Non-Preferred; fp_ECN: BGA100XD_SMDC9_SM9.msg

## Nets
GND: C3.2 C4.2 C5.2 C6.2 C7.2 C8.2 C11.2 C13.2 C15.2 C17.2 C20.2 C22.2 C38.2 C39.2 C41.2 C42.2 C43.2 C44.2 C45.2 C46.2 C47.2 C55.2 C57.2 C604.1 C605.1 C607.1 C673.2 C674.2 C675.2 C676.2 C677.2 J41.12(DM0_N_DBIO_N) J41.33(DM1_N_DBI1_N) J41.54(DM2_N_DBI2_N) J41.75(DM3_N_DBI3_N) J41.96(DBI8_N) J41.178(DM4_N_DBI4_N) J41.199(DM5_N_DBI5_N) J41.220(DM6_N_DBI6_N) J41.241(DM7_N_DBI7_N) J41.256(SA0) J41.260(SA1) J42.12(DM0_N_DBIO_N) J42.33(DM1_N_DBI1_N) J42.54(DM2_N_DBI2_N) J42.75(DM3_N_DBI3_N) J42.96(DBI8_N) J42.178(DM4_N_DBI4_N) J42.199(DM5_N_DBI5_N) J42.220(DM6_N_DBI6_N) J42.241(DM7_N_DBI7_N) J42.256(SA0) R16.2 R19.2 R31.1 R32.1 R33.1 R132.2 R184.2 R241.1 R257.1 R283.1 R290.1 R334.2 R598.1 R1127.2 R1138.2 R1325.1 R1327.1 R1334.1 R1357.2 U118.TH ; also on sheet 1 2 3 4 11 12 13 14 15 16 17 18 19 20 22 23 24 25 26 27 28 31 32 41 42 45 46 47 48 49 50 51 52 53 54 55 56 57 58 59 65 66 67 68 69 70 71 72 73 74 75 77 79 81 82 83 84 86 87 88 92
P0V6_DDR4_VREF_CA_CHAB: C3.1 C41.1 J41.164(VREFCA) J42.164(VREFCA) ; also on sheet 15
P1V05_COMBINED: R345.1 R650.1 ; also on sheet 1 3 4 16 18 19 41 42 45 47 48 50 51 52 54 55 56 71 74 75 79 84 92 94
P1V05_PCH: R609.1 ; also on sheet 50 51 52 67 74 84
P2V5_VPP: C8.1 C15.1 C42.1 C45.1 J41.255(VDDSPD) J42.255(VDDSPD) J42.260(SA1) ; also on sheet 11 15 19 25 75
P3V3: R105.2 R115.2 R116.2 R129.2 R135.1 R141.2 R231.2 R240.2 R252.2 R287.2 R593.1 R612.2 R1336.1 ; also on sheet 4 19 20 32 41 42 46 47 49 50 52 55 56 67 74 77 81
P3V3_STBY: C5.1 C604.2 C605.2 C607.2 C673.1 C674.1 C675.1 C676.1 C677.1 R20.1 R22.1 R23.1 R24.1 R27.2 R30.2 R119.2 R162.2 R175.1 R176.1 R193.2 R201.1 R207.2 R247.2 R279.2 R365.2 R366.2 R578.2 R1125.1 R1137.1 R1313.2 R1323.1 R1324.1 R1326.2 R1328.2 R1329.2 R1332.2 ; also on sheet 3 4 13 14 16 18 19 20 22 24 25 26 27 28 31 32 41 52 55 56 57 58 59 65 67 68 69 70 71 72 73 74 75 77 79 81 82 84 86 87 88 92
P3V3_STBY_VCC: R1329.1 U118.1(NCI||VCC)
P3V3_STBY_VDD1: R1332.1 R1333.2 U118.8(VDD1)
P3V3_STBY_VDD2: R1328.1 U118.14(NCI||VDD)
P3V3_STBY_VDD3: R27.1 U118.22(VDD2)
P3V_BAT: R197.1 R222.1 ; also on sheet 13 18 41 52 72
BATLOW_N: U92.L4(IO_28) ; also on sheet 20 65 71
FAST_THROTTLE_N_R: R1137.2 U92.F3(IO_9) ; also on sheet 47 65 71
FM_ADR_TRIGGER_PCH_N: R1138.1 ; also on sheet 47
FM_BDXDE_CATERR_LVT3_N: U92.D2(IO_5) ; also on sheet 47 56 72
FM_BDXDE_ERR0_LVT3_N: U92.F1(IO_8) ; also on sheet 47 56 72
FM_BDXDE_ERR1_LVT3_N: U92.E2(IO_7) ; also on sheet 47 56 72
FM_BDXDE_ERR2_LVT3_N: U92.D3(IO_6) ; also on sheet 56 72
FM_BDXDE_ME_DRIVE_N: R365.1 U92.G1(IO_10) ; also on sheet 47
FM_BDXDE_SLP3_N: R1159.1 U92.D10(IO_64) ; also on sheet 14 20 71
FM_BDXDE_SLP3_N_R: R1159.2 ; also on sheet 47
FM_BDXDE_SLP4_N: R839.1 U92.B11(IO_57) ; also on sheet 20 71
FM_BDXDE_SLP4_N_R: R247.1 R839.2 ; also on sheet 47
FM_BDXDE_SLP_A_N: R201.2 ; also on sheet 47
FM_BDXDE_SMI_N: R135.2 ; also on sheet 47 67
FM_BDXDE_THERMTRIP_N: R609.2 ; also on sheet 47 56
FM_CPLD_BDXDE_RESET_N: U92.K10(IO_24) ; also on sheet 56
FM_CPLD_BDXDE_THERMTRIP_N: U92.L1(IO_25) ; also on sheet 56 65 72
FM_CPLD_CLEAR_LATCH: U92.J10(IO_74) ; also on sheet 71
FM_CPLD_CPU_DIMM_EVENT_CO_N: U92.A1(IO_37) ; also on sheet 19 72
FM_CPLD_DEBUG_MODE: R1125.2 R1127.1 U92.K3(IO_18)
FM_CPLD_FAST_PROCHOT_N_R: U92.A4(IO_40) ; also on sheet 14
FM_CPLD_FIVR_FAULT: U92.L6(IO_30) ; also on sheet 56 72
FM_CPLD_GPIO27_MGPIO6: R279.1 U92.K4(IO_19) ; also on sheet 47
FM_CPLD_P0V6_VTT_DIMM_EN_R: U92.L9(IO_32) ; also on sheet 14
FM_CPLD_P1V2_VDDQ_EN_R: U92.C11(IO_62) ; also on sheet 14
FM_CPLD_P1V05_COMBINED_EN_R: U92.B3(IO_49) ; also on sheet 14
FM_CPLD_P1V05_PCH_EN_R: U92.D11(IO_65) ; also on sheet 14
FM_CPLD_P1V5_PCH_EN_R: U92.F9(IO_68) ; also on sheet 14
FM_CPLD_P2V5_VPP_EN_R: U92.C6(IO_59) ; also on sheet 14
FM_CPLD_P3V3_EN_N_R: U92.L10(IO_33) ; also on sheet 14
FM_CPLD_P3V3_PWRGD: U92.H3(IO_14) ; also on sheet 32
FM_CPLD_PCH_THERMTRIP_N: U92.K11(IO_76) ; also on sheet 67
FM_CPLD_PCIE_RESET_N: U92.K8(IO_35_DEV_CLRn) ; also on sheet 58
FM_CPLD_PVCCIN_EN_R: U92.H9(IO_71) ; also on sheet 14
FM_CPLD_PVCCKRHV_EN_R: U92.B5(IO_51) ; also on sheet 14
FM_CPLD_PVCCSCFUSESUS_EN_R: U92.A8(IO_44) ; also on sheet 14
FM_CPLD_RSMRST_N: U92.A11(IO_47) ; also on sheet 81
FM_CPLD_THERMTRIP_N_LATCH: U92.K9(IO_23) ; also on sheet 71
FM_CPLD_VR_HOT_N: U92.A7(IO_43) ; also on sheet 72
FM_CPU_THROTTLE_N_R: R319.1 U92.L3(IO_27)
FM_CPU_THROTTLE_N_R1: R319.2 ; also on sheet 67
FM_NMI_EVENT_N_NOA_CLK2: R141.1 ; also on sheet 47 67
FM_PCH_HOT_LVT3_N: U92.L2(IO_26) ; also on sheet 56 71
FM_SRC1CLKRQB_GP18: R115.1 ; also on sheet 47
FM_TPM_BADD: R19.1 U118.6(GPIO)
FM_TPM_PIN2: R28.2 R1327.2 U118.2(GND1)
FM_TPM_PIN9: R30.1 R32.2 U118.9(GND2)
FM_TPM_PIN10: R1326.1 U118.10(NCI4)
FM_TPM_PIN16: R31.2 U118.16(NCI||GND)
FM_TPM_PIN23: R1325.2 U118.23(GND3)
FM_TPM_PIN26: R33.2 U118.26(NCI10)
FM_TPM_PIN31: R26.1 U118.31(NCI13)
FM_TPM_PIN32: R1334.2 U118.32(GND4)
FP_PWR_BTN_BUF_N: U92.A3(IO_39) ; also on sheet 69 72 73
FP_RST_BTN_BUF_N: U92.A6(IO_42) ; also on sheet 69 71
H_BDXDE_PROCHOT_DISABLE: R366.1 U92.G2(IO_11) ; also on sheet 47
H_MEM_EVENT_CO_N: J41.134(EVENT_N) J42.134(EVENT_N) ; also on sheet 19
IRQ_IBMC_PCH_SMI_LPC_N: R578.1 ; also on sheet 47 71
IRQ_ILB_SEIRQ_BDE: R129.1 ; also on sheet 19 47
IRQ_PIRQA_N: R10.1 R28.1 R1335.1 ; also on sheet 47
IRQ_PIRQA_TPM_CHIP_N: R10.2 R1324.2 U118.18(PIRQ#)
IRQ_TPM_N: R1335.2 U118.13(NCI7)
LED_CPLD_D1: U92.L8(IO_36_DEV_OE) ; also on sheet 77
M_A_ACT_N: J41.114(ACT_N) ; also on sheet 43
M_A_ALERT_N: J41.116(ALERT_N) ; also on sheet 43
M_A_BA<0>: J41.150(BA0) ; also on sheet 43
M_A_BA<1>: J41.145(BA1) ; also on sheet 43
M_A_BG<0>: J41.115(BG0) ; also on sheet 43
M_A_BG<1>: J41.113(BG1) ; also on sheet 43
M_A_CK_DN<0>: J41.139(CK0N) ; also on sheet 43
M_A_CK_DN<2>: J41.140(CK1N) ; also on sheet 43
M_A_CK_DP<0>: J41.137(CK0P) ; also on sheet 43
M_A_CK_DP<2>: J41.138(CK1P) ; also on sheet 43
M_A_CKE<0>: J41.109(CKE0) ; also on sheet 43
M_A_CKE<1>: J41.110(CKE1) ; also on sheet 43
M_A_CS_N<0>: J41.149(CS0_N) ; also on sheet 43
M_A_CS_N<1>: J41.157(CS1_N) ; also on sheet 43
M_A_DQ<0>: J41.8(DQ0) ; also on sheet 43
M_A_DQ<1>: J41.7(DQ1) ; also on sheet 43
M_A_DQ<2>: J41.20(DQ2) ; also on sheet 43
M_A_DQ<3>: J41.21(DQ3) ; also on sheet 43
M_A_DQ<4>: J41.4(DQ4) ; also on sheet 43
M_A_DQ<5>: J41.3(DQ5) ; also on sheet 43
M_A_DQ<6>: J41.16(DQ6) ; also on sheet 43
M_A_DQ<7>: J41.17(DQ7) ; also on sheet 43
M_A_DQ<8>: J41.28(DQ8) ; also on sheet 43
M_A_DQ<9>: J41.29(DQ9) ; also on sheet 43
M_A_DQ<10>: J41.41(DQ10) ; also on sheet 43
M_A_DQ<11>: J41.42(DQ11) ; also on sheet 43
M_A_DQ<12>: J41.24(DQ12) ; also on sheet 43
M_A_DQ<13>: J41.25(DQ13) ; also on sheet 43
M_A_DQ<14>: J41.38(DQ14) ; also on sheet 43
M_A_DQ<15>: J41.37(DQ15) ; also on sheet 43
M_A_DQ<16>: J41.50(DQ16) ; also on sheet 43
M_A_DQ<17>: J41.49(DQ17) ; also on sheet 43
M_A_DQ<18>: J41.62(DQ18) ; also on sheet 43
M_A_DQ<19>: J41.63(DQ19) ; also on sheet 43
M_A_DQ<20>: J41.46(DQ20) ; also on sheet 43
M_A_DQ<21>: J41.45(DQ21) ; also on sheet 43
M_A_DQ<22>: J41.58(DQ22) ; also on sheet 43
M_A_DQ<23>: J41.59(DQ23) ; also on sheet 43
M_A_DQ<24>: J41.70(DQ24) ; also on sheet 43
M_A_DQ<25>: J41.71(DQ25) ; also on sheet 43
M_A_DQ<26>: J41.83(DQ26) ; also on sheet 43
M_A_DQ<27>: J41.84(DQ27) ; also on sheet 43
M_A_DQ<28>: J41.66(DQ28) ; also on sheet 43
M_A_DQ<29>: J41.67(DQ29) ; also on sheet 43
M_A_DQ<30>: J41.79(DQ30) ; also on sheet 43
M_A_DQ<31>: J41.80(DQ31) ; also on sheet 43
M_A_DQ<32>: J41.174(DQ32) ; also on sheet 43
M_A_DQ<33>: J41.173(DQ33) ; also on sheet 43
M_A_DQ<34>: J41.187(DQ34) ; also on sheet 43
M_A_DQ<35>: J41.186(DQ35) ; also on sheet 43
M_A_DQ<36>: J41.170(DQ36) ; also on sheet 43
M_A_DQ<37>: J41.169(DQ37) ; also on sheet 43
M_A_DQ<38>: J41.183(DQ38) ; also on sheet 43
M_A_DQ<39>: J41.182(DQ39) ; also on sheet 43
M_A_DQ<40>: J41.195(DQ40) ; also on sheet 43
M_A_DQ<41>: J41.194(DQ41) ; also on sheet 43
M_A_DQ<42>: J41.207(DQ42) ; also on sheet 43
M_A_DQ<43>: J41.208(DQ43) ; also on sheet 43
M_A_DQ<44>: J41.191(DQ44) ; also on sheet 43
M_A_DQ<45>: J41.190(DQ45) ; also on sheet 43
M_A_DQ<46>: J41.203(DQ46) ; also on sheet 43
M_A_DQ<47>: J41.204(DQ47) ; also on sheet 43
M_A_DQ<48>: J41.216(DQ48) ; also on sheet 43
M_A_DQ<49>: J41.215(DQ49) ; also on sheet 43
M_A_DQ<50>: J41.228(DQ50) ; also on sheet 43
M_A_DQ<51>: J41.229(DQ51) ; also on sheet 43
M_A_DQ<52>: J41.211(DQ52) ; also on sheet 43
M_A_DQ<53>: J41.212(DQ53) ; also on sheet 43
M_A_DQ<54>: J41.224(DQ54) ; also on sheet 43
M_A_DQ<55>: J41.225(DQ55) ; also on sheet 43
M_A_DQ<56>: J41.237(DQ56) ; also on sheet 43
M_A_DQ<57>: J41.236(DQ57) ; also on sheet 43
M_A_DQ<58>: J41.249(DQ58) ; also on sheet 43
M_A_DQ<59>: J41.250(DQ59) ; also on sheet 43
M_A_DQ<60>: J41.232(DQ60) ; also on sheet 43
M_A_DQ<61>: J41.233(DQ61) ; also on sheet 43
M_A_DQ<62>: J41.245(DQ62) ; also on sheet 43
M_A_DQ<63>: J41.246(DQ63) ; also on sheet 43
M_A_DQS_DN<0>: J41.11(DQS0N) ; also on sheet 43
M_A_DQS_DN<1>: J41.32(DQS1N) ; also on sheet 43
M_A_DQS_DN<2>: J41.53(DQS2N) ; also on sheet 43
M_A_DQS_DN<3>: J41.74(DQS3N) ; also on sheet 43
M_A_DQS_DN<4>: J41.177(DQS4N) ; also on sheet 43
M_A_DQS_DN<5>: J41.198(DQS5N) ; also on sheet 43
M_A_DQS_DN<6>: J41.219(DQS6N) ; also on sheet 43
M_A_DQS_DN<7>: J41.240(DQS7N) ; also on sheet 43
M_A_DQS_DN<8>: J41.95(DQS8N) ; also on sheet 43
M_A_DQS_DP<0>: J41.13(DQS0P) ; also on sheet 43
M_A_DQS_DP<1>: J41.34(DQS1P) ; also on sheet 43
M_A_DQS_DP<2>: J41.55(DQS2P) ; also on sheet 43
M_A_DQS_DP<3>: J41.76(DQS3P) ; also on sheet 43
M_A_DQS_DP<4>: J41.179(DQS4P) ; also on sheet 43
M_A_DQS_DP<5>: J41.200(DQS5P) ; also on sheet 43
M_A_DQS_DP<6>: J41.221(DQS6P) ; also on sheet 43
M_A_DQS_DP<7>: J41.242(DQS7P) ; also on sheet 43
M_A_DQS_DP<8>: J41.97(DQS8P) ; also on sheet 43
M_A_ECC<0>: J41.92(CB0_NC) ; also on sheet 43
M_A_ECC<1>: J41.91(CB1_NC) ; also on sheet 43
M_A_ECC<2>: J41.101(CB2_NC) ; also on sheet 43
M_A_ECC<3>: J41.105(CB3_NC) ; also on sheet 43
M_A_ECC<4>: J41.88(CB4_NC) ; also on sheet 43
M_A_ECC<5>: J41.87(CB5_NC) ; also on sheet 43
M_A_ECC<6>: J41.100(CB6_NC) ; also on sheet 43
M_A_ECC<7>: J41.104(CB7_NC) ; also on sheet 43
M_A_MA<0>: J41.144(A0) ; also on sheet 43
M_A_MA<1>: J41.133(A1) ; also on sheet 43
M_A_MA<2>: J41.132(A2) ; also on sheet 43
M_A_MA<3>: J41.131(A3) ; also on sheet 43
M_A_MA<4>: J41.128(A4) ; also on sheet 43
M_A_MA<5>: J41.126(A5) ; also on sheet 43
M_A_MA<6>: J41.127(A6) ; also on sheet 43
M_A_MA<7>: J41.122(A7) ; also on sheet 43
M_A_MA<8>: J41.125(A8) ; also on sheet 43
M_A_MA<9>: J41.121(A9) ; also on sheet 43
M_A_MA<10>: J41.146(A10_AP) ; also on sheet 43
M_A_MA<11>: J41.120(A11) ; also on sheet 43
M_A_MA<12>: J41.119(A12) ; also on sheet 43
M_A_MA<13>: J41.158(A13) ; also on sheet 43
M_A_MA<14>: J41.151(A14_WE_N) ; also on sheet 43
M_A_MA<15>: J41.156(A15_CAS_N) ; also on sheet 43
M_A_MA<16>: J41.152(A16_RAS_N) ; also on sheet 43
M_A_ODT<0>: J41.155(ODT0) ; also on sheet 43
M_A_ODT<1>: J41.161(ODT1) ; also on sheet 43
M_A_PAR: J41.143(PARITY) ; also on sheet 43
M_AB_RESET_N: J41.108(RESET_N) J42.108(RESET_N) ; also on sheet 18
M_B_ACT_N: J42.114(ACT_N) ; also on sheet 44
M_B_ALERT_N: J42.116(ALERT_N) ; also on sheet 44
M_B_BA<0>: J42.150(BA0) ; also on sheet 44
M_B_BA<1>: J42.145(BA1) ; also on sheet 44
M_B_BG<0>: J42.115(BG0) ; also on sheet 44
M_B_BG<1>: J42.113(BG1) ; also on sheet 44
M_B_CK_DN<0>: J42.139(CK0N) ; also on sheet 44
M_B_CK_DN<2>: J42.140(CK1N) ; also on sheet 44
M_B_CK_DP<0>: J42.137(CK0P) ; also on sheet 44
M_B_CK_DP<2>: J42.138(CK1P) ; also on sheet 44
M_B_CKE<0>: J42.109(CKE0) ; also on sheet 44
M_B_CKE<1>: J42.110(CKE1) ; also on sheet 44
M_B_CS_N<0>: J42.149(CS0_N) ; also on sheet 44
M_B_CS_N<1>: J42.157(CS1_N) ; also on sheet 44
M_B_DQ<0>: J42.8(DQ0) ; also on sheet 44
M_B_DQ<1>: J42.7(DQ1) ; also on sheet 44
M_B_DQ<2>: J42.20(DQ2) ; also on sheet 44
M_B_DQ<3>: J42.21(DQ3) ; also on sheet 44
M_B_DQ<4>: J42.4(DQ4) ; also on sheet 44
M_B_DQ<5>: J42.3(DQ5) ; also on sheet 44
M_B_DQ<6>: J42.16(DQ6) ; also on sheet 44
M_B_DQ<7>: J42.17(DQ7) ; also on sheet 44
M_B_DQ<8>: J42.28(DQ8) ; also on sheet 44
M_B_DQ<9>: J42.29(DQ9) ; also on sheet 44
M_B_DQ<10>: J42.41(DQ10) ; also on sheet 44
M_B_DQ<11>: J42.42(DQ11) ; also on sheet 44
M_B_DQ<12>: J42.24(DQ12) ; also on sheet 44
M_B_DQ<13>: J42.25(DQ13) ; also on sheet 44
M_B_DQ<14>: J42.38(DQ14) ; also on sheet 44
M_B_DQ<15>: J42.37(DQ15) ; also on sheet 44
M_B_DQ<16>: J42.50(DQ16) ; also on sheet 44
M_B_DQ<17>: J42.49(DQ17) ; also on sheet 44
M_B_DQ<18>: J42.62(DQ18) ; also on sheet 44
M_B_DQ<19>: J42.63(DQ19) ; also on sheet 44
M_B_DQ<20>: J42.46(DQ20) ; also on sheet 44
M_B_DQ<21>: J42.45(DQ21) ; also on sheet 44
M_B_DQ<22>: J42.58(DQ22) ; also on sheet 44
M_B_DQ<23>: J42.59(DQ23) ; also on sheet 44
M_B_DQ<24>: J42.70(DQ24) ; also on sheet 44
M_B_DQ<25>: J42.71(DQ25) ; also on sheet 44
M_B_DQ<26>: J42.83(DQ26) ; also on sheet 44
M_B_DQ<27>: J42.84(DQ27) ; also on sheet 44
M_B_DQ<28>: J42.66(DQ28) ; also on sheet 44
M_B_DQ<29>: J42.67(DQ29) ; also on sheet 44
M_B_DQ<30>: J42.79(DQ30) ; also on sheet 44
M_B_DQ<31>: J42.80(DQ31) ; also on sheet 44
M_B_DQ<32>: J42.174(DQ32) ; also on sheet 44
M_B_DQ<33>: J42.173(DQ33) ; also on sheet 44
M_B_DQ<34>: J42.187(DQ34) ; also on sheet 44
M_B_DQ<35>: J42.186(DQ35) ; also on sheet 44
M_B_DQ<36>: J42.170(DQ36) ; also on sheet 44
M_B_DQ<37>: J42.169(DQ37) ; also on sheet 44
M_B_DQ<38>: J42.183(DQ38) ; also on sheet 44
M_B_DQ<39>: J42.182(DQ39) ; also on sheet 44
M_B_DQ<40>: J42.195(DQ40) ; also on sheet 44
M_B_DQ<41>: J42.194(DQ41) ; also on sheet 44
M_B_DQ<42>: J42.207(DQ42) ; also on sheet 44
M_B_DQ<43>: J42.208(DQ43) ; also on sheet 44
M_B_DQ<44>: J42.191(DQ44) ; also on sheet 44
M_B_DQ<45>: J42.190(DQ45) ; also on sheet 44
M_B_DQ<46>: J42.203(DQ46) ; also on sheet 44
M_B_DQ<47>: J42.204(DQ47) ; also on sheet 44
M_B_DQ<48>: J42.216(DQ48) ; also on sheet 44
M_B_DQ<49>: J42.215(DQ49) ; also on sheet 44
M_B_DQ<50>: J42.228(DQ50) ; also on sheet 44
M_B_DQ<51>: J42.229(DQ51) ; also on sheet 44
M_B_DQ<52>: J42.211(DQ52) ; also on sheet 44
M_B_DQ<53>: J42.212(DQ53) ; also on sheet 44
M_B_DQ<54>: J42.224(DQ54) ; also on sheet 44
M_B_DQ<55>: J42.225(DQ55) ; also on sheet 44
M_B_DQ<56>: J42.237(DQ56) ; also on sheet 44
M_B_DQ<57>: J42.236(DQ57) ; also on sheet 44
M_B_DQ<58>: J42.249(DQ58) ; also on sheet 44
M_B_DQ<59>: J42.250(DQ59) ; also on sheet 44
M_B_DQ<60>: J42.232(DQ60) ; also on sheet 44
M_B_DQ<61>: J42.233(DQ61) ; also on sheet 44
M_B_DQ<62>: J42.245(DQ62) ; also on sheet 44
M_B_DQ<63>: J42.246(DQ63) ; also on sheet 44
M_B_DQS_DN<0>: J42.11(DQS0N) ; also on sheet 44
M_B_DQS_DN<1>: J42.32(DQS1N) ; also on sheet 44
M_B_DQS_DN<2>: J42.53(DQS2N) ; also on sheet 44
M_B_DQS_DN<3>: J42.74(DQS3N) ; also on sheet 44
M_B_DQS_DN<4>: J42.177(DQS4N) ; also on sheet 44
M_B_DQS_DN<5>: J42.198(DQS5N) ; also on sheet 44
M_B_DQS_DN<6>: J42.219(DQS6N) ; also on sheet 44
M_B_DQS_DN<7>: J42.240(DQS7N) ; also on sheet 44
M_B_DQS_DN<8>: J42.95(DQS8N) ; also on sheet 44
M_B_DQS_DP<0>: J42.13(DQS0P) ; also on sheet 44
M_B_DQS_DP<1>: J42.34(DQS1P) ; also on sheet 44
M_B_DQS_DP<2>: J42.55(DQS2P) ; also on sheet 44
M_B_DQS_DP<3>: J42.76(DQS3P) ; also on sheet 44
M_B_DQS_DP<4>: J42.179(DQS4P) ; also on sheet 44
M_B_DQS_DP<5>: J42.200(DQS5P) ; also on sheet 44
M_B_DQS_DP<6>: J42.221(DQS6P) ; also on sheet 44
M_B_DQS_DP<7>: J42.242(DQS7P) ; also on sheet 44
M_B_DQS_DP<8>: J42.97(DQS8P) ; also on sheet 44
M_B_ECC<0>: J42.92(CB0_NC) ; also on sheet 44
M_B_ECC<1>: J42.91(CB1_NC) ; also on sheet 44
M_B_ECC<2>: J42.101(CB2_NC) ; also on sheet 44
M_B_ECC<3>: J42.105(CB3_NC) ; also on sheet 44
M_B_ECC<4>: J42.88(CB4_NC) ; also on sheet 44
M_B_ECC<5>: J42.87(CB5_NC) ; also on sheet 44
M_B_ECC<6>: J42.100(CB6_NC) ; also on sheet 44
M_B_ECC<7>: J42.104(CB7_NC) ; also on sheet 44
M_B_MA<0>: J42.144(A0) ; also on sheet 44
M_B_MA<1>: J42.133(A1) ; also on sheet 44
M_B_MA<2>: J42.132(A2) ; also on sheet 44
M_B_MA<3>: J42.131(A3) ; also on sheet 44
M_B_MA<4>: J42.128(A4) ; also on sheet 44
M_B_MA<5>: J42.126(A5) ; also on sheet 44
M_B_MA<6>: J42.127(A6) ; also on sheet 44
M_B_MA<7>: J42.122(A7) ; also on sheet 44
M_B_MA<8>: J42.125(A8) ; also on sheet 44
M_B_MA<9>: J42.121(A9) ; also on sheet 44
M_B_MA<10>: J42.146(A10_AP) ; also on sheet 44
M_B_MA<11>: J42.120(A11) ; also on sheet 44
M_B_MA<12>: J42.119(A12) ; also on sheet 44
M_B_MA<13>: J42.158(A13) ; also on sheet 44
M_B_MA<14>: J42.151(A14_WE_N) ; also on sheet 44
M_B_MA<15>: J42.156(A15_CAS_N) ; also on sheet 44
M_B_MA<16>: J42.152(A16_RAS_N) ; also on sheet 44
M_B_ODT<0>: J42.155(ODT0) ; also on sheet 44
M_B_ODT<1>: J42.161(ODT1) ; also on sheet 44
M_B_PAR: J42.143(PARITY) ; also on sheet 44
PD_P1V2_VDDQ_SEL_N: R184.1 ; also on sheet 47
PECI_ID[0]: R334.1 R345.2 ; also on sheet 47
PU_BMBUSY_N_GPIO0: R593.2 ; also on sheet 47
PU_BMCINIT: R650.2 ; also on sheet 47
PU_DSWODVREN: R197.2 ; also on sheet 47
PU_GP50_GSXCLK: R105.1 ; also on sheet 47
PU_GP54_GSXSREST_N: R116.1 ; also on sheet 47
PU_GPIO72_BATLOW_N: R176.2 ; also on sheet 47
PU_INTVRMEN: R222.2 ; also on sheet 47
PU_PME_N: R207.1 ; also on sheet 47
PU_RI_N: R193.1 ; also on sheet 47
PU_SPI_BDE_CS1_N: R119.1 ; also on sheet 47
PU_SUSACK_N: R175.2 ; also on sheet 47
PU_SUSWARN_N_GPIO30: R1313.1 ; also on sheet 47
PV_DDR_VTTAB: C17.1 C22.1 C39.1 C57.1 ; also on sheet 11 15 22
PV_VDDRAB: C4.1 C6.1 C7.1 C11.1 C13.1 C20.1 C38.1 C43.1 C44.1 C46.1 C47.1 C55.1 ; also on sheet 11 15 22 23 24 51 74
PWRGD_APWROK_R: U92.B2(IO_48) ; also on sheet 14
PWRGD_CPLD_BDXDE_LAN_R: U92.G10(IO_70) ; also on sheet 14
PWRGD_CPU: R132.1 ; also on sheet 18 47 54 56
PWRGD_CPU0_CPLD: U92.A2(IO_38) ; also on sheet 56 71
PWRGD_P0V6_VTT_DIMM: U92.L7(IO_31) ; also on sheet 22
PWRGD_P1V2_VDDQ: U92.D9(IO_63) ; also on sheet 24
PWRGD_P1V05_COMBINED: U92.B4(IO_50) U92.B8(IO_54) U92.B10(IO_56) ; also on sheet 3
PWRGD_P1V05_PCH: U92.E10(IO_66) U92.J6(IO_16) ; also on sheet 84
PWRGD_P1V5_PCH: U92.F11(IO_69) ; also on sheet 31
PWRGD_P2V5_VPP: U92.C10(IO_61) ; also on sheet 25
PWRGD_PCH_PWROK_R: U92.H11(IO_73) ; also on sheet 14
PWRGD_PVCCIN: U92.H10(IO_72) ; also on sheet 3 71
PWRGD_PVCCKRHV: U92.B6(IO_52) ; also on sheet 26
PWRGD_PVCCSCFUSESUS: U92.A10(IO_46) ; also on sheet 27
REV_BDE_ID0: R287.1 R290.2 ; also on sheet 47
REV_BDE_ID1: R598.2 R612.1 ; also on sheet 47
RFU: J41.166(RFU)
RFU (page 047 DDR4 SODIMM CHB_1): J42.166(RFU)
RSM_RST_N_R: U92.A5(IO_41) ; also on sheet 14
RST_CPLD_CPU_RSMRST_N: U92.K7(IO_22) ; also on sheet 14
RST_PLTRST_CHIP: R1322.2 U118.17(RST#)
RST_PLTRST_N: R1322.1 R1333.1 U92.L11(IO_34) ; also on sheet 47 67
SKU_BDE_ID0: R252.1 R283.2 ; also on sheet 47
SKU_BDE_ID1: R240.1 R241.2 ; also on sheet 47
SKU_BDE_ID2: R231.1 R257.2 ; also on sheet 47
SLP_SUS_STAT_N: R1258.1 ; also on sheet 71 82
SLP_SUS_STAT_N_R: R1258.2 ; also on sheet 47
SMB_HOST_2V5_CLK_R3: J41.253(SCL) J42.253(SCL) ; also on sheet 75
SMB_HOST_2V5_DAT_R3: J41.254(SDA) J42.254(SDA) ; also on sheet 75
SMB_HOST_XDP_CLK: R17.2 ; also on sheet 18 54 71 73
SMB_HOST_XDP_DAT: R18.2 ; also on sheet 18 54 71 73
SMB_INA230_ALRT_N_PROCHOT: U92.H2(IO_13) ; also on sheet 71 86
SMB_TPM_CHIP_CLK: R17.1 U118.30(NC2)
SMB_TPM_CHIP_DAT: R18.1 U118.29(NC1)
SPI_BDE_CS2_N: R162.1 R1320.1 ; also on sheet 47
SPI_BDE_MISO: R1319.1 ; also on sheet 47 59
SPI_TPM_CLK_CHIP: R1323.2 U118.19(SCLK) ; also on sheet 47
SPI_TPM_CS_CHIP_N: R22.2 R1320.2 U118.20(CS#)
SPI_TPM_MISO_CHIP: R23.2 R1319.2 U118.24(MISO)
SPI_TPM_MOSI_CHIP: R24.2 U118.21(MOSI) ; also on sheet 47
TOM_NCI2: R1331.2 U118.4(NCI2)
TP_CPLD_CATERR_N_LATCH: U92.K6(IO_21)
TP_CPLD_ERROR0_N_LATCH: U92.B1(IO_1)
TP_CPLD_ERROR1_N_LATCH: U92.C1(IO_2)
TP_CPLD_ERROR2_N_LATCH: U92.C2(IO_3)
TP_CPLD_P3V3_STBY_PHY_PWRGD: U92.A9(IO_45)
TP_CPLD_PLTRST_N_LATCH: U92.D1(IO_4)
TP_CPLD_PROCHOT_N_LATCH: U92.H1(IO_12)
TP_CPLD_PVCCGBE_EN: U92.B7(IO_53)
TP_CPLD_PVCCSCSUS_EN: U92.B9(IO_55)
TP_FM_CPLD_M2_DEVSLP: U92.K5(IO_20)
TP_FM_CPLD_P1V05_PROC_IO_EN_N: U92.E11(IO_67)
TP_PWRGD_P1V8: U92.L5(IO_29)
TPM_NCI11: R16.1 R20.2 U118.27(NCI11)
TPM_PP: R1330.2 U118.7(PP)
TPM_PRSNT_N: R26.2 R1330.1 R1331.1 R1336.2 R1357.1 ; also on sheet 47
XDP_CPU_SYSPWROK_R: U92.J11(IO_75) ; also on sheet 14

Not connected (* = marked no-connect by the designer): J41 162(C0_CS2_N_NC)* 165(C1_CS3_N_NC)*; J42 162(C0_CS2_N_NC)* 165(C1_CS3_N_NC)*; U118 3(NCI1)* 5(NCI3)* 11(NCI5)* 12(NCI6)* 15(NCI8)* 25(NCI9)* 28(NCI12)*

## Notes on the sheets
sheet 60
- SPD ADDRES : 0XA0
- DESIGN NOTE : PLCAE BWTWEEN DIMM SLOT.
- DDR4 SODIMM CHA_1
sheet 61
- SPD ADDRES : 0XA4
- DESIGN NOTE : PLCAE BWTWEEN DIMM SLOT.
- DDR4 SODIMM CHB_1
sheet 62
- Infineon SLB9670
- BOM NOTE:
  Depop R1330 for SLB9670
- BOM NOTE:
  Stuff pull up resistor for I2C interface
- BOM NOTE:
  Stuff resistor for I2C interface
- TPM SLB9670
sheet 63
- PECI_ID[2:0]=000B
- DESIGN NOTE : PD FOR VBOOT = 1.2V.
- ID1
- ID0
- EVT
- 0
- 0
- DVT
- 0
- 1
- PVT
- 1
- 0
- BDX-DE LPC,SPI,GPIO,INT,PWR_2
sheet 64
- DESIGN NOTE :
- Below latch signals are useless.
  Will left to non-connect.
- FM_CPLD_CATERR_N_LATCH
  FM_CPLD_CLEAR_LATCH
  FM_CPLD_ERROR0_N_LATCH
  FM_CPLD_ERROR1_N_LATCH
  FM_CPLD_ERROR2_N_LATCH
  FM_CPLD_PCHHOT_N_GP74_LATCH
  FM_CPLD_PLTRST_N_LATCH
  FM_CPLD_PROCHOT_N_LATCH
  FM_CPLD_THERMTRIP_N_LATCH
- 0
- DESIGN NOTE :
  HIGH : VR ENABLE
  LOW : NORMAL MODE
- DESIGN NOTE :
  Add Testpoint for CPLD LED for DEBUG.
- DESIGN NOTE :
- PWRGD_P1V8 : Left non-connect.
  PWRGD_P0V6_VTT_DIMM : This need to modify CPLD.
  FM_CPLD_P3V3_STBY_PHY_PWRGD : Left non-connect.
  FM_CPLD_PVCCSCSUS_EN : Left non-connect.
  LED_CPLD_D1 : Add a test point for this.
  LED_CPLD_D2 : Add a test point for this.
  LED_CPLD_D3 : Add a test point for this.
  LED_CPLD_D4 : Add a test point for this.
- CPLD_1
